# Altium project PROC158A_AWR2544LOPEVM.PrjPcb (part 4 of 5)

## Sheet PROC158A_FTDI.SchDoc
size 431 x 279 mm; Date: Not shown in title block; ApprovedBy: Not shown in title block; CheckedBy: Not shown in title block; Author: Not shown in title block; CompanyName: Not shown in title block; Engineer: Not shown in title block; Organization: Not shown in title block; Address1: Not shown in title block; Address2: Not shown in title block; Address3: Not shown in title block; Address4: Not shown in title block; DocumentNumber: 17; Revision: Use project parameter SCH_Rev; SheetNumber: 17; SheetTotal: 24; PageSetup: Record=PageOptions¦CenterHorizontal=True¦CenterVertical=True¦PrintScale=1.00¦XCorrection=1.00¦YCorrection=1.00¦PrintKind=0¦BorderSize=5000000¦LeftOffset=0¦BottomOffset=0¦Orientation=2¦PaperLength=1000¦PaperWidth=1000¦Scale=100¦PaperSource=15¦PrintQuality=600¦MediaType=1¦DitherType=10¦PaperKind=Letter¦PrintScaleMode=1
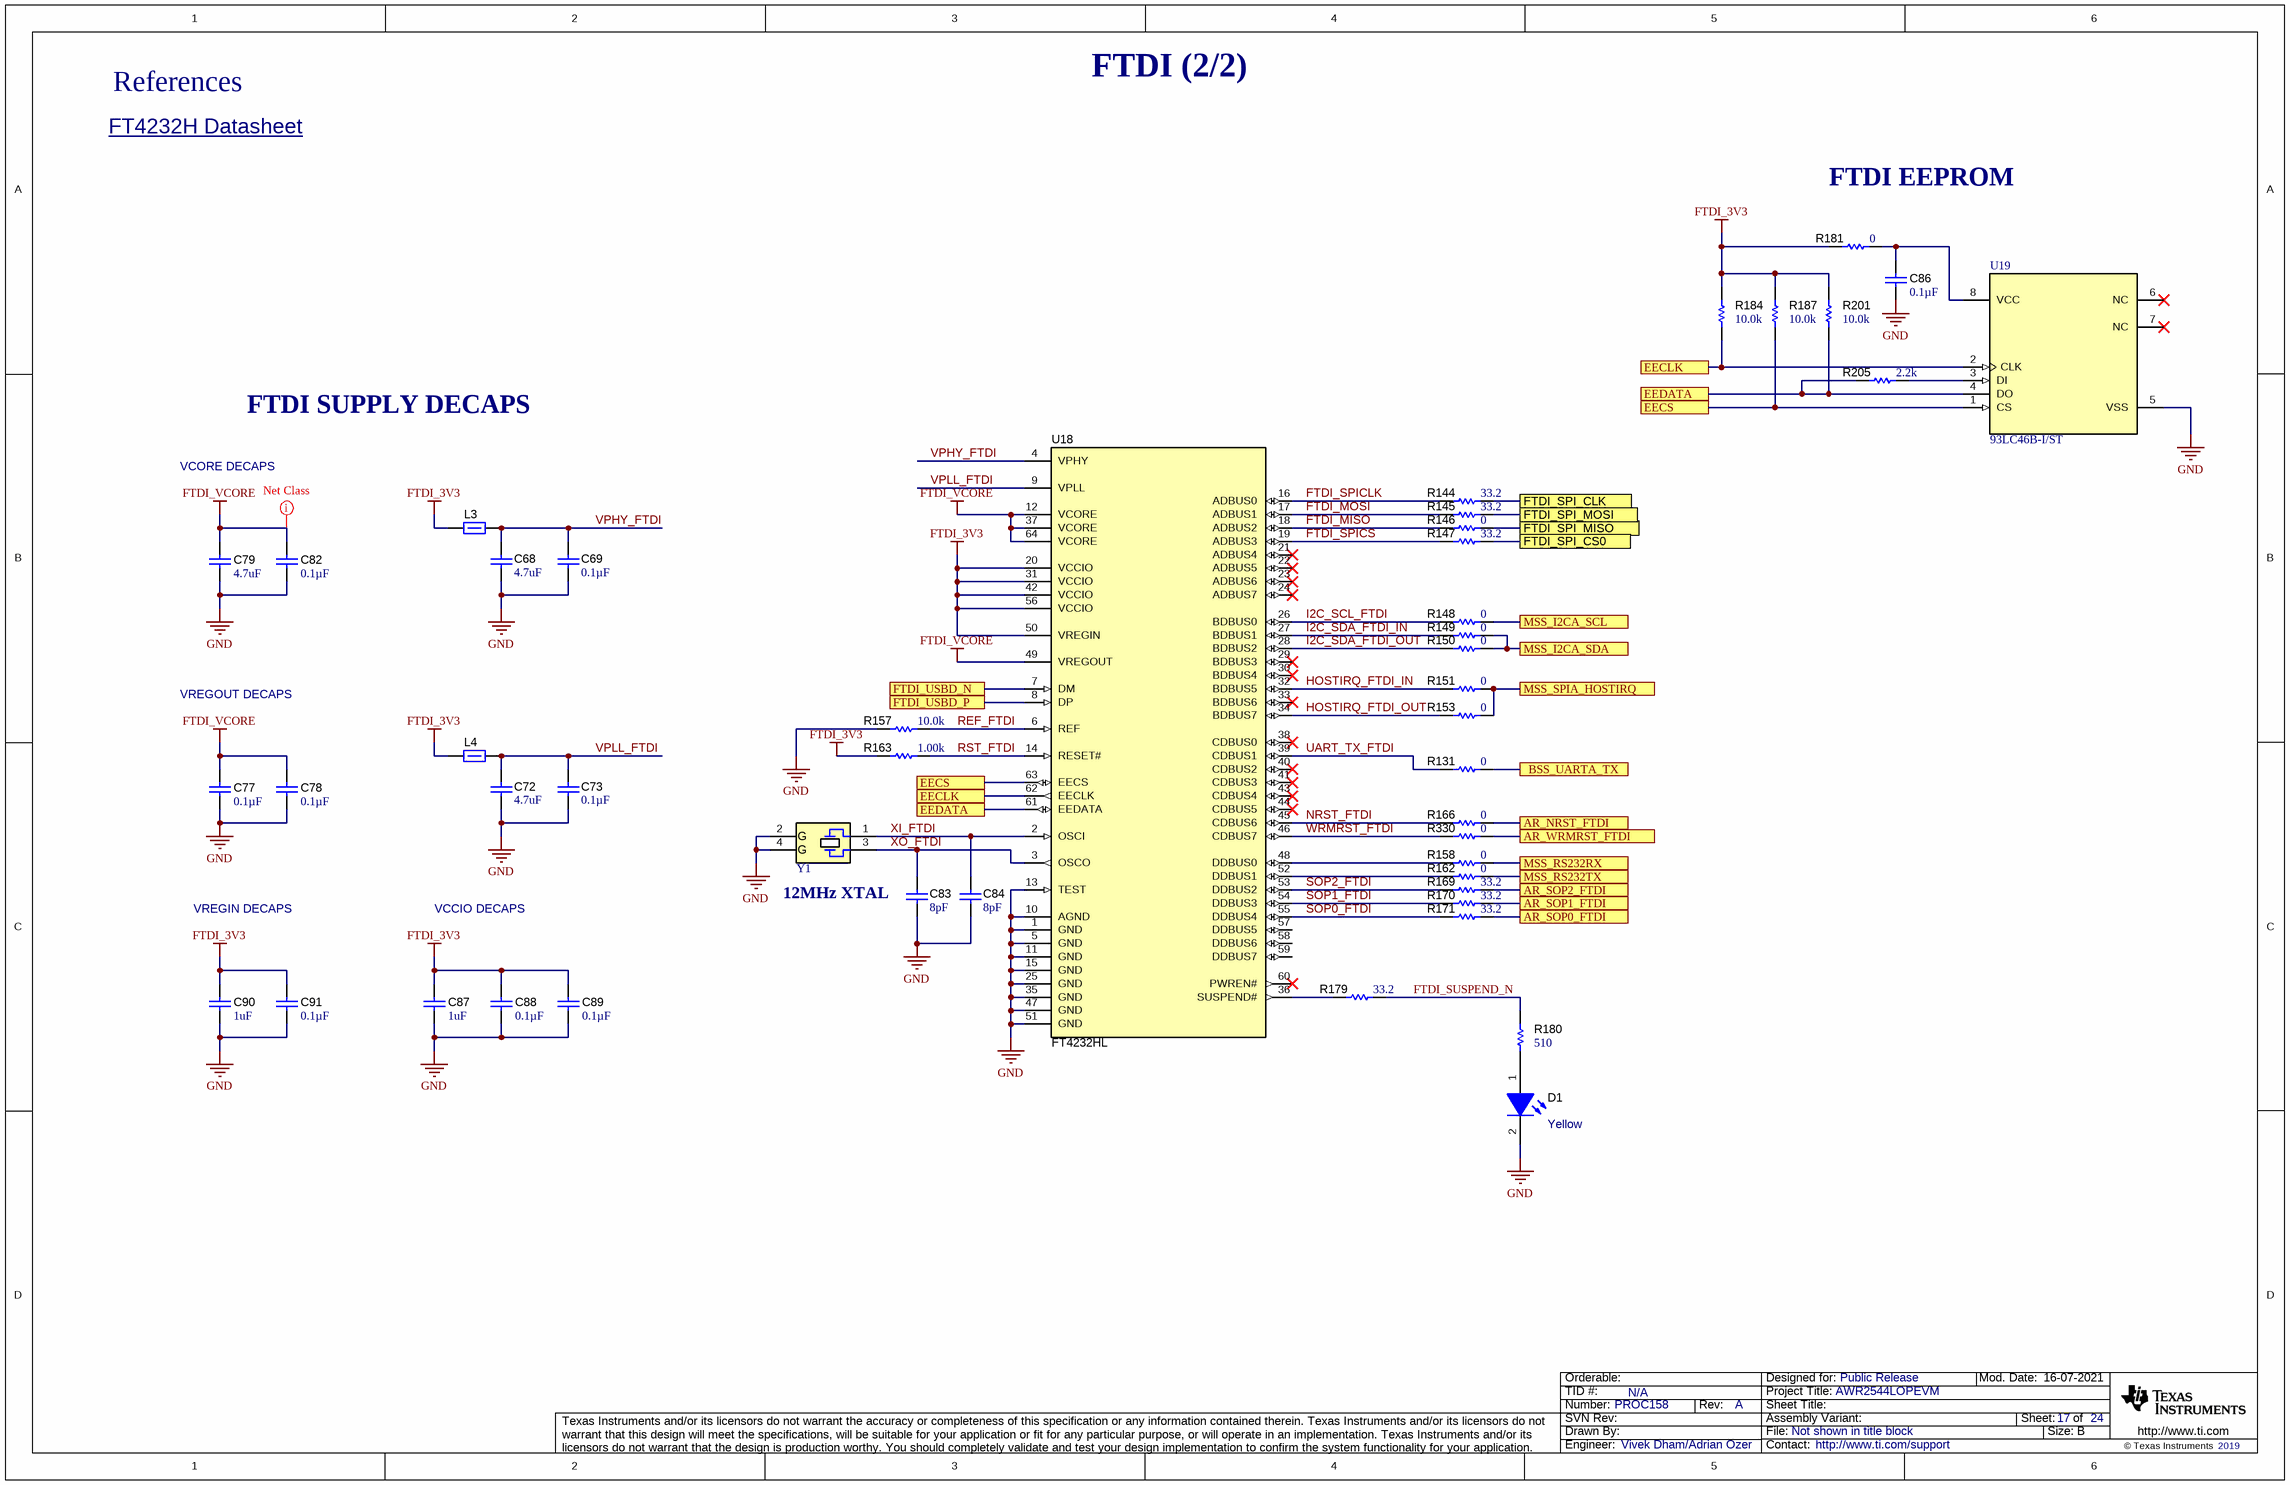
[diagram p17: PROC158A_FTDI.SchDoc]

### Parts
C68  ValueDisplayed: 4.7uF  [0603L]  (hidden comment: C1608X7S1A475K080AC)
C69  ValueDisplayed: 0.1µF  [0402L]  (hidden comment: C0402C104K8RACTU)
C72  ValueDisplayed: 4.7uF  [0603L]  (hidden comment: C1608X7S1A475K080AC)
C73  ValueDisplayed: 0.1µF  [0402L]  (hidden comment: C0402C104K8RACTU)
C77  ValueDisplayed: 0.1µF  [0402L]  (hidden comment: C0402C104K8RACTU)
C78  ValueDisplayed: 0.1µF  [0402L]  (hidden comment: C0402C104K8RACTU)
C79  ValueDisplayed: 4.7uF  [0603L]  (hidden comment: C1608X7S1A475K080AC)
C82  ValueDisplayed: 0.1µF  [0402L]  (hidden comment: C0402C104K8RACTU)
C83  Cap_F: 8pF  [0402L]  (hidden comment: GCM1555C1H8R0DA16D)
C84  Cap_F: 8pF  [0402L]  (hidden comment: GCM1555C1H8R0DA16D)
C86  ValueDisplayed: 0.1µF  [0402L]  (hidden comment: C0402C104K8RACTU)
C87  ValueDisplayed: 1uF  [0603L]  (hidden comment: GCM188R71C105KA64D)
C88  ValueDisplayed: 0.1µF  [0402L]  (hidden comment: C0402C104K8RACTU)
C89  ValueDisplayed: 0.1µF  [0402L]  (hidden comment: C0402C104K8RACTU)
C90  ValueDisplayed: 1uF  [0603L]  (hidden comment: GCM188R71C105KA64D)
C91  ValueDisplayed: 0.1µF  [0402L]  (hidden comment: C0402C104K8RACTU)
D1  value Yellow  [TLMx1000_Yellow]  (hidden comment: TLMY1000-GS08)
L3  BLM15HG601SN1D  [0402L]  (value not drawn)
L4  BLM15HG601SN1D  [0402L]  (value not drawn)
R131  ValueDisplayed: 0  [0402L]  (hidden comment: ERJ-2GE0R00X)
R144  ValueDisplayed: 33.2  [0402L]  (hidden comment: CRCW040233R2FKED)
R145  ValueDisplayed: 33.2  [0402L]  (hidden comment: CRCW040233R2FKED)
R146  ValueDisplayed: 0  [0402L]  (hidden comment: ERJ-2GE0R00X)
R147  ValueDisplayed: 33.2  [0402L]  (hidden comment: CRCW040233R2FKED)
R148  ValueDisplayed: 0  [0402L]  (hidden comment: ERJ-2GE0R00X)
R149  ValueDisplayed: 0  [0402L]  (hidden comment: ERJ-2GE0R00X)
R150  ValueDisplayed: 0  [0402L]  (hidden comment: ERJ-2GE0R00X)
R151  ValueDisplayed: 0  [0402L]  (hidden comment: ERJ-2GE0R00X)
R153  ValueDisplayed: 0  [0402L]  (hidden comment: ERJ-2GE0R00X)
R157  ValueDisplayed: 10.0k  [0402L]  (hidden comment: CRCW040210K0FKED)
R158  ValueDisplayed: 0  [0402L]  (hidden comment: ERJ-2GE0R00X)
R162  ValueDisplayed: 0  [0402L]  (hidden comment: ERJ-2GE0R00X)
R163  ValueDisplayed: 1.00k  [0402L]  (hidden comment: CRCW04021K00FKED)
R166  ValueDisplayed: 0  [0402L]  (hidden comment: ERJ-2GE0R00X)
R169  ValueDisplayed: 33.2  [0402L]  (hidden comment: CRCW040233R2FKED)
R170  ValueDisplayed: 33.2  [0402L]  (hidden comment: CRCW040233R2FKED)
R171  ValueDisplayed: 33.2  [0402L]  (hidden comment: CRCW040233R2FKED)
R179  ValueDisplayed: 33.2  [0402L]  (hidden comment: CRCW040233R2FKED)
R180  ValueDisplayed: 510  [0402L]  (hidden comment: ERJ-2GEJ511X)
R181  ValueDisplayed: 0  [0402L]  (hidden comment: ERJ-2GE0R00X)
R184  ValueDisplayed: 10.0k  [0402L]  (hidden comment: CRCW040210K0FKED)
R187  ValueDisplayed: 10.0k  [0402L]  (hidden comment: CRCW040210K0FKED)
R201  ValueDisplayed: 10.0k  [0402L]  (hidden comment: CRCW040210K0FKED)
R205  ValueDisplayed: 2.2k  [0402L]  (hidden comment: CRCW04022K20JNED)
R330  ValueDisplayed: 0  [0402L]  (hidden comment: ERJ-2GE0R00X)
U18  FT4232HL  [LQFP64_N]
U19  93LC46B-I/ST  [TSSOP-8]
Y1  NX3225SA-12.000M-STD-CRS-2  [NDK_NX3225SA]  (value not drawn)

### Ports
AR_NRST_FTDI, AR_SOP0_FTDI, AR_SOP1_FTDI, AR_SOP2_FTDI, AR_WRMRST_FTDI, BSS_UARTA_TX, EECLK, EECS, EEDATA, FTDI_SPI_CLK, FTDI_SPI_CS0, FTDI_SPI_MISO, FTDI_SPI_MOSI, FTDI_USBD_N, FTDI_USBD_P, MSS_I2CA_SCL, MSS_I2CA_SDA, MSS_RS232RX, MSS_RS232TX, MSS_SPIA_HOSTIRQ

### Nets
FTDI_3V3: C87.1 C88.1 C89.1 C90.1 C91.1 L3.1 L4.1 R163.1 R181.2 R184.2 R187.2 R201.2 U18.20(VCCIO) U18.31(VCCIO) U18.42(VCCIO) U18.50(VREGIN) U18.56(VCCIO)
FTDI_VCORE: C77.1 C78.1 C79.1 C82.1 U18.12(VCORE) U18.37(VCORE) U18.49(VREGOUT) U18.64(VCORE)
GND: C68.2 C69.1 C72.2 C73.1 C77.2 C78.2 C79.2 C82.2 C83.2 C84.2 C86.2 C87.2 C88.2 C89.2 C90.2 C91.2 D1.2(K) R157.1 U18.1(GND) U18.5(GND) U18.10(AGND) U18.11(GND) U18.13(TEST) U18.15(GND) U18.25(GND) U18.35(GND) U18.47(GND) U18.51(GND) U19.5(VSS) Y1.2(GND) Y1.4(GND)
AR_NRST_FTDI: R166.2 ; port AR_NRST_FTDI
AR_SOP0_FTDI: R171.2 ; port AR_SOP0_FTDI
AR_SOP1_FTDI: R170.2 ; port AR_SOP1_FTDI
AR_SOP2_FTDI: R169.2 ; port AR_SOP2_FTDI
AR_WRMRST_FTDI: R330.2 ; port AR_WRMRST_FTDI
BSS_UARTA_TX: R131.1 ; port BSS_UARTA_TX
EECLK: R184.1 U18.62(EECLK) U19.2(CLK) ; port EECLK
EECS: R187.1 U18.63(EECS) U19.1(CS) ; port EECS
EEDATA: R201.1 R205.1 U18.61(EEDATA) U19.4(DO) ; port EEDATA
FTDI_MISO: R146.1 U18.18(ADBUS2)
FTDI_MOSI: R145.1 U18.17(ADBUS1)
FTDI_SPI_CLK: R144.2 ; port FTDI_SPI_CLK
FTDI_SPI_CS0: R147.2 ; port FTDI_SPI_CS0
FTDI_SPI_MISO: R146.2 ; port FTDI_SPI_MISO
FTDI_SPI_MOSI: R145.2 ; port FTDI_SPI_MOSI
FTDI_SPICLK: R144.1 U18.16(ADBUS0)
FTDI_SPICS: R147.1 U18.19(ADBUS3)
FTDI_SUSPEND_N: R179.2 R180.2
FTDI_USBD_N: U18.7(DM) ; port FTDI_USBD_N
FTDI_USBD_P: U18.8(DP) ; port FTDI_USBD_P
HOSTIRQ_FTDI_IN: R151.1 U18.32(BDBUS5)
HOSTIRQ_FTDI_OUT: R153.1 U18.34(BDBUS7)
I2C_SCL_FTDI: R148.1 U18.26(BDBUS0)
I2C_SDA_FTDI_IN: R149.1 U18.27(BDBUS1)
I2C_SDA_FTDI_OUT: R150.1 U18.28(BDBUS2)
MSS_I2CA_SCL: R148.2 ; port MSS_I2CA_SCL
MSS_I2CA_SDA: R149.2 R150.2 ; port MSS_I2CA_SDA
MSS_RS232RX: R158.2 ; port MSS_RS232RX
MSS_RS232TX: R162.2 ; port MSS_RS232TX
MSS_SPIA_HOSTIRQ: R151.2 R153.2 ; port MSS_SPIA_HOSTIRQ
NRST_FTDI: R166.1 U18.45(CDBUS6)
REF_FTDI: R157.2 U18.6(REF)
RST_FTDI: R163.2 U18.14(RESET#)
SOP0_FTDI: R171.1 U18.55(DDBUS4)
SOP1_FTDI: R170.1 U18.54(DDBUS3)
SOP2_FTDI: R169.1 U18.53(DDBUS2)
UART_TX_FTDI: R131.2 U18.39(CDBUS1)
VPHY_FTDI: C68.1 C69.2 L3.2 U18.4(VPHY)
VPLL_FTDI: C72.1 C73.2 L4.2 U18.9(VPLL)
WRMRST_FTDI: R330.1 U18.46(CDBUS7)
XI_FTDI: C84.1 U18.2(OSCI) Y1.1
XO_FTDI: C83.1 U18.3(OSCO) Y1.3
NetC86_1: C86.1 R181.1 U19.8(VCC)
NetD1_1: D1.1(A) R180.1
NetR158_1: R158.1 U18.48(DDBUS0)
NetR162_1: R162.1 U18.52(DDBUS1)
NetR179_1: R179.1 U18.36(SUSPEND#)
NetR205_2: R205.2 U19.3(DI)

Not connected (* = marked no-connect by the designer): U18 21(ADBUS4)* 22(ADBUS5)* 23(ADBUS6)* 24(ADBUS7)* 29(BDBUS3)* 30(BDBUS4)* 33(BDBUS6)* 38(CDBUS0)* 40(CDBUS2)* 41(CDBUS3)* 43(CDBUS4)* 44(CDBUS5)* 57(DDBUS5) 58(DDBUS6) 59(DDBUS7) 60(PWREN#)*; U19 6(NC)* 7(NC)*

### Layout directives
net class PWR: FTDI_VCORE

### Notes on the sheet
- References
- FTDI (2/2)
- FT4232H Datasheet <https://www.ftdichip.com/Support/Documents/DataSheets/ICs/DS_FT4232H.pdf>
- FTDI EEPROM
- FTDI SUPPLY DECAPS
- VCORE DECAPS
- VREGOUT DECAPS
- 12MHz XTAL
- VREGIN DECAPS
- VCCIO DECAPS

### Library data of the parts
C68 C72 C79 = CMP-0007058-4: CAP, CERM, 4.7 uF, 10 V, +/- 10%, X7S, 0603; Manufacturer: TDK; TaMin_C: -55°C; Polarized: N; SizeAreaWB_mm2: 4.68; Value1: Unknown; U/M: EA; Value: 4.7uF; TaMax_C: 125°C; SizeZ_mm: 1; SizeX_mm: 1.6; SizeY_mm: 0.8; Cap_Case: 0603; Value2: 10V; SizeArea_mm2: 1.28; CompType: Capacitor; Cap_F: 4.7µF; AEC Category: Q200
C69 C73 C77 C78 C82 C86 C88 C89 C91 = CMP-0078241-1: CAP, CERM, 0.1 µF, 10 V,+/- 10%, X7R, 0402; Manufacturer: Kemet; TaMin_C: -55°C; Polarized: N; SizeAreaWB_mm2: 3; U/M: EA; Value: 0.1uF; TaMax_C: 125°C; SizeZ_mm: 0.6; SizeX_mm: 1; SizeY_mm: 0.5; Cap_Case: 0402; Value2: 10V; CompType: Capacitor; Cap_F: 100nF; AEC Category: Q200
C83 C84 = CMP-0087060-3: Cap Ceramic 8pF 50V C0G 0.5pF SMD 0402 125C Paper T/R; Manufacturer: Murata Electronics North America; AEC Qualified: Yes; TempCo: 30ppm/°C; AEC Grade: Grade 1; SizeZ_mm: 0.55mm
C87 C90 = CMP-0007136-5: CAP, CERM, 1 uF, 16 V, +/- 10%, X7R, AEC-Q200 Grade 1, 0603; Manufacturer: MuRata; TaMin_C: -55°C; Polarized: N; SizeAreaWB_mm2: 4.68; Value1: Unknown; U/M: EA; Value: 1uF; TaMax_C: 125°C; SizeZ_mm: 1; SizeX_mm: 1.6; SizeY_mm: 0.8; Cap_Case: 0603; Value2: 16V; SizeArea_mm2: 1.28; CompType: Capacitor; AEC Qualified: Y; Cap_F: 1µF; AEC Category: Q200
D1 = CMP-0078196-2: LED, Yellow, SMD; Manufacturer: Vishay-Semiconductor; Tjmax_C: 120°C; SizeAreaWB_mm2: 4.68; Vr_V: 6V; Power_TotalModule: 40mW; Angle: 160; SizeArea_mm2: 1.28; Ir_A: 10µA; SizeZ_mm: 0.65; Io_A: 2mA; Vf_V: 1.8V; SizeY_mm: 0.8; Value1: .04W; SizeX_mm: 1.6; Type: AlInGaP
L3 L4 = CMP-0081523-1: Ferrite Bead, 600 ohm @ 100 MHz, 0.3 A, 0402; Manufacturer: MuRata; SizeAreaWB_mm2: 3; SizeArea_mm2: 0.5; Value: 600 ohm; SizeZ_mm: 0.6; Imax_A: 3dA; ZTyp@100MHz_Ohm: 600; Value2: 0.3A; Value1: 0.7 ohm; DCR_ohm: 7d; SizeX_mm: 1; Ztyp@1GHz_Ohm: 1k
R131 R158 R162 = CMP-0026992-3: RES, 0, 5%, 0.1 W, AEC-Q200 Grade 0, 0402; Manufacturer: Panasonic; Power_W: 100mW; TempCo: 600 ppm/C; Value_Code: 0000; Value: 0; EIA_Code: E24; SizeX_mm: 1; SizeY_mm: 0.5; SizeZ_mm: 0.6; Value2: 0.1W; CompType: Resistor; AEC Qualified: Y; VDC_V: 50V; AEC Category: Q200; SizeAreaWB_mm2: 3; INSTALLATION: DNP
R144 R145 R147 R169-R171 R179 = CMP-0026299-2: RES, 33.2, 1%, 0.063 W, AEC-Q200 Grade 0, 0402; Manufacturer: Vishay-Dale; Power_W: 63mW; TempCo: 100 ppm/C; Value_Code: 33R2; Value: 33.2; EIA_Code: E96; SizeX_mm: 1; SizeY_mm: 0.5; SizeZ_mm: 0.6; Value2: 0.063W; AEC Qualified: Y; VDC_V: 50V; AEC Category: Q200; AEC Grade: 0
R146 R148-R151 R153 R166 R181 R330 = CMP-0026992-3: RES, 0, 5%, 0.1 W, AEC-Q200 Grade 0, 0402; Manufacturer: Panasonic; Power_W: 100mW; TempCo: 600 ppm/C; Value_Code: 0000; Value: 0; EIA_Code: E24; SizeX_mm: 1; SizeY_mm: 0.5; SizeZ_mm: 0.6; Value2: 0.1W; AEC Qualified: Y; VDC_V: 50V; AEC Category: Q200; SizeAreaWB_mm2: 3
R157 R184 R187 R201 = CMP-0025958-3: RES, 10.0 k, 1%, 0.063 W, AEC-Q200 Grade 0, 0402; Manufacturer: Vishay-Dale; Power_W: 63mW; TempCo: 100 ppm/C; Value_Code: 10k0; Value: 10.0k; EIA_Code: E96; Res_ohm: 10k; SizeX_mm: 1; SizeY_mm: 0.5; SizeZ_mm: 0.6; Value2: 0.063W; AEC Qualified: Y; VDC_V: 50V; AEC Category: Q200; AEC Grade: 0
R163 = CMP-0026071-3: RES, 1.00 k, 1%, 0.063 W, AEC-Q200 Grade 0, 0402; Manufacturer: Vishay-Dale; Power_W: 63mW; TempCo: 100 ppm/C; Value_Code: 1k00; Value: 1.00k; EIA_Code: E96; Res_ohm: 1k; SizeX_mm: 1; SizeY_mm: 0.5; SizeZ_mm: 0.6; Value2: 0.063W; AEC Qualified: Y; VDC_V: 50V; AEC Category: Q200; AEC Grade: 0
R180 = CMP-0078212-1: RES, 510, 5%, 0.1 W, AEC-Q200 Grade 0, 0402; Manufacturer: Panasonic; Value_Code: 510R; SizeArea_mm2: 0.5; AEC Qualified: Y; AEC Category: Q200; Value: 510; SizeZ_mm: 0.6; EIA_Code: E24; TempCo: 200 ppm/C; AEC Grade: 0; Power_W: 100mW; VDC_V: 50V; Value2: 0.1W; U/M: EA; SizeX_mm: 1
R205 = CMP-0026890-5: RES, 2.2 k, 5%, 0.063 W, AEC-Q200 Grade 0, 0402; Manufacturer: Vishay-Dale; Power_W: 63mW; TempCo: 200 ppm/C; Value_Code: 2k20; Value: 2.2k; EIA_Code: E24; SizeX_mm: 1; SizeY_mm: 0.5; SizeZ_mm: 0.6; Value2: 0.063W; AEC Qualified: Y; VDC_V: 50V; AEC Category: Q200; AEC Grade: 0
U18 = CMP-0004747-1: Quad High Speed USB to Multipurpose UART/MPSSE IC; Manufacturer: FTDI
U19 = CMP-0081524-1: 1K Microwire Compatible Serial EEPROM, TSSOP-8; Manufacturer: Microchip; SizeArea_mm2: 19.2; SizeAreaWB_mm2: 42; SizeY_mm: 3; SizeZ_mm: 1.2; SizeX_mm: 6.4
Y1 = CMP-0081529-1: Crystal, 12 MHz, 15 ppm, 8 pF, AEC-Q200 Grade 1, SMD; Manufacturer: NDK; TaMin_C: -40°C; Frequency Tolerance: 15 ppm; Frequency Stability: 50 ppm; Load Capacitance: 8 pF; Frequency_Fixed: 12MHz; TaMax_C: 125°C; AEC Qualified: Y; AEC Grade: 1; AEC Category: Q200

## Sheet PROC158A_XDS110 Interface_1A.SchDoc
size 431 x 279 mm; Date: Not shown in title block; ApprovedBy: Not shown in title block; CheckedBy: Not shown in title block; Author: Not shown in title block; CompanyName: Not shown in title block; Engineer: Not shown in title block; Organization: Not shown in title block; Address1: Not shown in title block; Address2: Not shown in title block; Address3: Not shown in title block; Address4: Not shown in title block; DocumentNumber: 18; Revision: Use project parameter SCH_Rev; SheetNumber: 18; SheetTotal: 24; PageSetup: Record=PageOptions¦CenterHorizontal=True¦CenterVertical=True¦PrintScale=1.00¦XCorrection=1.00¦YCorrection=1.00¦PrintKind=0¦BorderSize=5000000¦LeftOffset=0¦BottomOffset=0¦Orientation=2¦PaperLength=1000¦PaperWidth=1000¦Scale=100¦PaperSource=15¦PrintQuality=600¦MediaType=1¦DitherType=10¦PaperKind=Letter¦PrintScaleMode=1
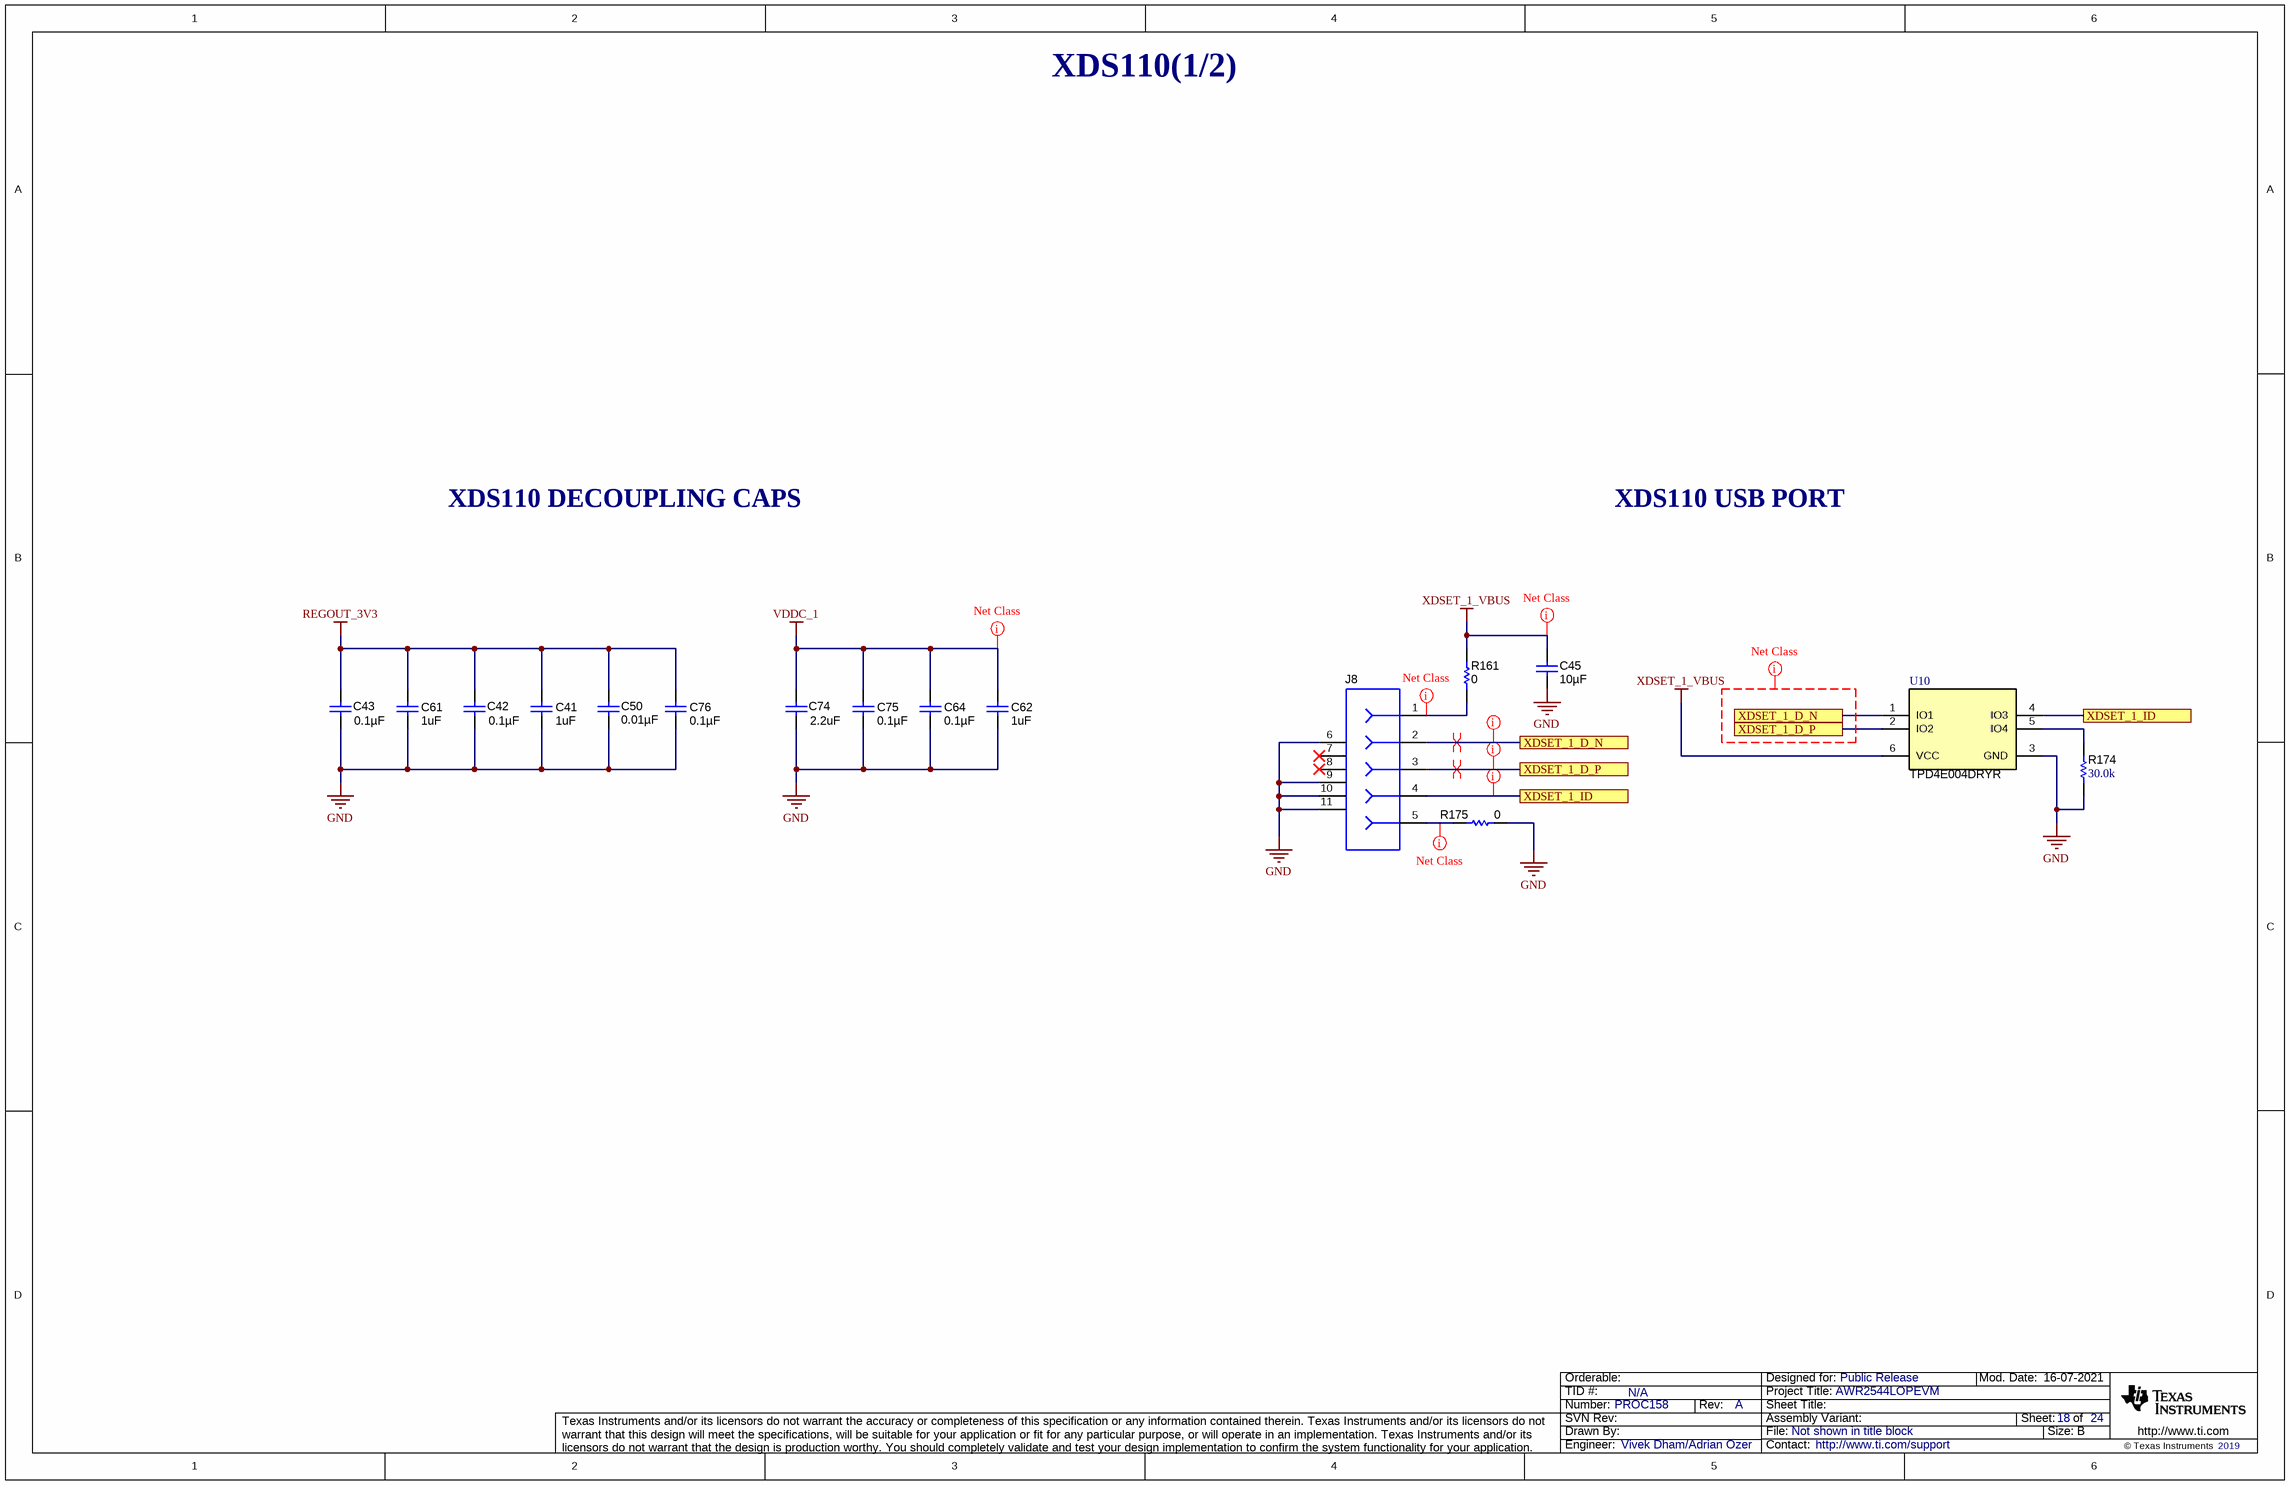
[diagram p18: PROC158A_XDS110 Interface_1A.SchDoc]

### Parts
C41  ValueDisplayed: 1uF  [0402_070]  (hidden comment: GCM155C71A105KE38D)
C42  ValueDisplayed: 0.1µF  [0402L]  (hidden comment: C0402C104K8RACTU)
C43  ValueDisplayed: 0.1µF  [0402L]  (hidden comment: C0402C104K8RACTU)
C45  Cap_F: 10µF  [0805L]  (hidden comment: CL21B106KOQNNNE)
C50  ValueDisplayed: 0.01µF  [0402L]  (hidden comment: C0402C103K4RACTU)
C61  ValueDisplayed: 1uF  [0402_070]  (hidden comment: GCM155C71A105KE38D)
C62  ValueDisplayed: 1uF  [0402_070]  (hidden comment: GCM155C71A105KE38D)
C64  ValueDisplayed: 0.1µF  [0402L]  (hidden comment: C0402C104K8RACTU)
C74  ValueDisplayed: 2.2uF  [0402_065L]  (hidden comment: C1005X7S1A225K050BC)
C75  ValueDisplayed: 0.1µF  [0402L]  (hidden comment: C0402C104K8RACTU)
C76  ValueDisplayed: 0.1µF  [0402L]  (hidden comment: C0402C104K8RACTU)
J8  105017-0001  [CONN_105017-0001]  (value not drawn)
R161  ValueDisplayed: 0  [0603L]  (hidden comment: MCT06030Z0000ZP500)
R174  ValueDisplayed: 30.0k  [0402L]  (hidden comment: CRCW040230K0FKED)
R175  ValueDisplayed: 0  [0603L]  (hidden comment: MCT06030Z0000ZP500)
U10  TPD4E004DRYR  [DRY0006A]

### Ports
XDSET_1_D_N, XDSET_1_D_P, XDSET_1_ID

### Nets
GND: C41.2 C42.1 C43.1 C45.2 C50.2 C61.2 C62.2 C64.1 C74.1 C75.1 C76.1 J8.6 J8.9 J8.10 J8.11 R174.1 R175.1 U10.3(GND)
REGOUT_3V3: C41.1 C42.2 C43.2 C50.1 C61.1 C76.2
VDDC_1: C62.1 C64.2 C74.2 C75.2
XDSET_1_VBUS: C45.1 R161.2 U10.6(VCC)
XDSET_1_D_N: J8.2 U10.1(IO1) ; port XDSET_1_D_N
XDSET_1_D_P: J8.3 U10.2(IO2) ; port XDSET_1_D_P
XDSET_1_ID: J8.4 U10.4(IO3) ; port XDSET_1_ID
NetJ8_1: J8.1 R161.1
NetJ8_5: J8.5 R175.2
NetR174_2: R174.2 U10.5(IO4)

Not connected (* = marked no-connect by the designer): J8 7* 8*

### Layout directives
differential pair: XDSET_1_D_N, XDSET_1_D_P
net class XDS_USB: XDSET_1_D_N, XDSET_1_D_P, XDSET_1_ID
net class PWR: NetJ8_1, NetJ8_5, VDDC_1, XDSET_1_VBUS
net class USB_DIFF: (no net found under the mark)

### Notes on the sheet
- XDS110(1/2)
- XDS110 DECOUPLING CAPS
- XDS110 USB PORT

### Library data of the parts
C41 C61 C62 = CMP-0006349-2: CAP, CERM, 1 uF, 10 V, +/- 10%, X7S, AEC-Q200 Grade 1, 0402; Manufacturer: MuRata; TaMin_C: -55°C; Polarized: N; SizeAreaWB_mm2: 3; Value1: Unknown; U/M: EA; Value: 1uF; TaMax_C: 125°C; SizeZ_mm: 0.7; SizeX_mm: 1; SizeY_mm: 0.5; Cap_Case: 0402; Value2: 10V; AEC Qualified: Y; Cap_F: 1µF; AEC Category: Q200
C42 C43 C64 C75 C76 = CMP-0078241-1: CAP, CERM, 0.1 µF, 10 V,+/- 10%, X7R, 0402; Manufacturer: Kemet; TaMin_C: -55°C; Polarized: N; SizeAreaWB_mm2: 3; U/M: EA; Value: 0.1uF; TaMax_C: 125°C; SizeZ_mm: 0.6; SizeX_mm: 1; SizeY_mm: 0.5; Cap_Case: 0402; Value2: 10V; Cap_F: 100nF; AEC Category: Q200
C45 = CMP-0007995-2: CAP, CERM, 10 uF, 16 V, +/- 10%, X7R, 0805; Manufacturer: Samsung Electro-Mechanics; TaMin_C: -55°C; Polarized: N; SizeAreaWB_mm2: 6.75; Value1: Unknown; U/M: EA; Value: 10uF; TaMax_C: 125°C; SizeZ_mm: 1.45; SizeX_mm: 2; SizeY_mm: 1.25; Cap_Case: 0805; Value2: 16V; SizeArea_mm2: 2.5; AEC Category: Q200
C50 = CMP-0078218-1: CAP, CERM, 0.01 µF, 16 V,+/- 10%, X7R, 0402; Manufacturer: Kemet; TaMin_C: -55°C; Polarized: N; Green_Lifecycle: Active; SizeAreaWB_mm2: 3; Green_REACh: Passed; U/M: EA; Value: 0.01uF; TaMax_C: 125°C; SizeZ_mm: 0.6; SizeX_mm: 1; SizeY_mm: 0.5; Cap_Case: 0402; Value2: 16V; Cap_F: 10nF; AEC Category: Q200
C74 = CMP-0006302-2: CAP, CERM, 2.2 uF, 10 V, +/- 10%, X7S, 0402; Manufacturer: TDK; TaMin_C: -55°C; ESR_ohm: 5.925m; Polarized: N; SizeAreaWB_mm2: 3; Value1: 0.005925 ohm; U/M: EA; Value: 2.2uF; TaMax_C: 125°C; SizeZ_mm: 0.65; SizeX_mm: 1; SizeY_mm: 0.5; Cap_Case: 0402_065; Value2: 10V; CompType: Capacitor; Cap_F: 2.2µF; IRMS_A: 2.05591A; AEC Category: Q200
J8 = CMP-0055293-1: Connector, Receptacle, Micro-USB Type B, R/A, Bottom Mount SMT; Manufacturer: Molex; CNHeader: FALSE; Green_Lifecycle: Active; Gender: Female; Green_REACh: Passed; CompType: USB; CT: TRUE
R161 R175 = CMP-0025884-3: RES, 0, 5%, 0.125 W, 0603; Manufacturer: Vishay/Beyschlag; Power_W: 125mW; TempCo: ppm/C; Value_Code: 0000; U/M: EA; Value: 0; EIA_Code: E24; SizeX_mm: 1.6; SizeY_mm: 0.8; SizeZ_mm: 1; Value2: 0.125W; SizeArea_mm2: 1.28; AEC Qualified: N; AEC Category: Q200
R174 = CMP-0078244-2: RES, 30.0 k, 1%, 0.063 W, AEC-Q200 Grade 0, 0402; Manufacturer: Vishay-Dale; Power_W: 63mW; Green_Lifecycle: Active; TempCo: 100 ppm/C; Value_Code: 30k0; Green_REACh: Passed; Value: 30.0k; Res_ohm: 30k; SizeX_mm: 1; SizeY_mm: 0.5; SizeZ_mm: 0.6; Value2: 0.063W; AEC Qualified: Y; VDC_V: 50V; AEC Grade: 0; AEC Category: Q200
U10 = CMP-0043115-3: 4-Channel ESD Protection Array for High-Speed Data Interfaces, DRY0006A (USON-6); Manufacturer: Texas Instruments; IO Leakage Current(nA): 1; USB High Speed: TRUE; IO Capacitance(Typ)(pF): 1.6; Eco-Plan: Green (RoHS & no Sb/Br); IEC 61000-4-2 Contact(+/- kV): 8; Breakdown Voltage(Min)(V): 6; IEC 61000-4-2 Air-Gap(+/- kV): 12; AEC Category: Q200; AEC Qualified: N; CompType: IC; SizeArea_mm2: 1.45; SizeAreaWB_mm2: 4.9; SizeX_mm: 1.0; SizeZ_mm: 0.6; Rating: Catalog

## Sheet PROC158A_XDS110 Interface_1B.SchDoc
size 431 x 279 mm; Date: Not shown in title block; ApprovedBy: Not shown in title block; CheckedBy: Not shown in title block; Author: Not shown in title block; CompanyName: Not shown in title block; Engineer: Not shown in title block; Organization: Not shown in title block; Address1: Not shown in title block; Address2: Not shown in title block; Address3: Not shown in title block; Address4: Not shown in title block; DocumentNumber: 19; Revision: Use project parameter SCH_Rev; SheetNumber: 19; SheetTotal: 24; PageSetup: Record=PageOptions¦CenterHorizontal=True¦CenterVertical=True¦PrintScale=1.00¦XCorrection=1.00¦YCorrection=1.00¦PrintKind=0¦BorderSize=5000000¦LeftOffset=0¦BottomOffset=0¦Orientation=2¦PaperLength=1000¦PaperWidth=1000¦Scale=100¦PaperSource=15¦PrintQuality=600¦MediaType=1¦DitherType=10¦PaperKind=Letter¦PrintScaleMode=1
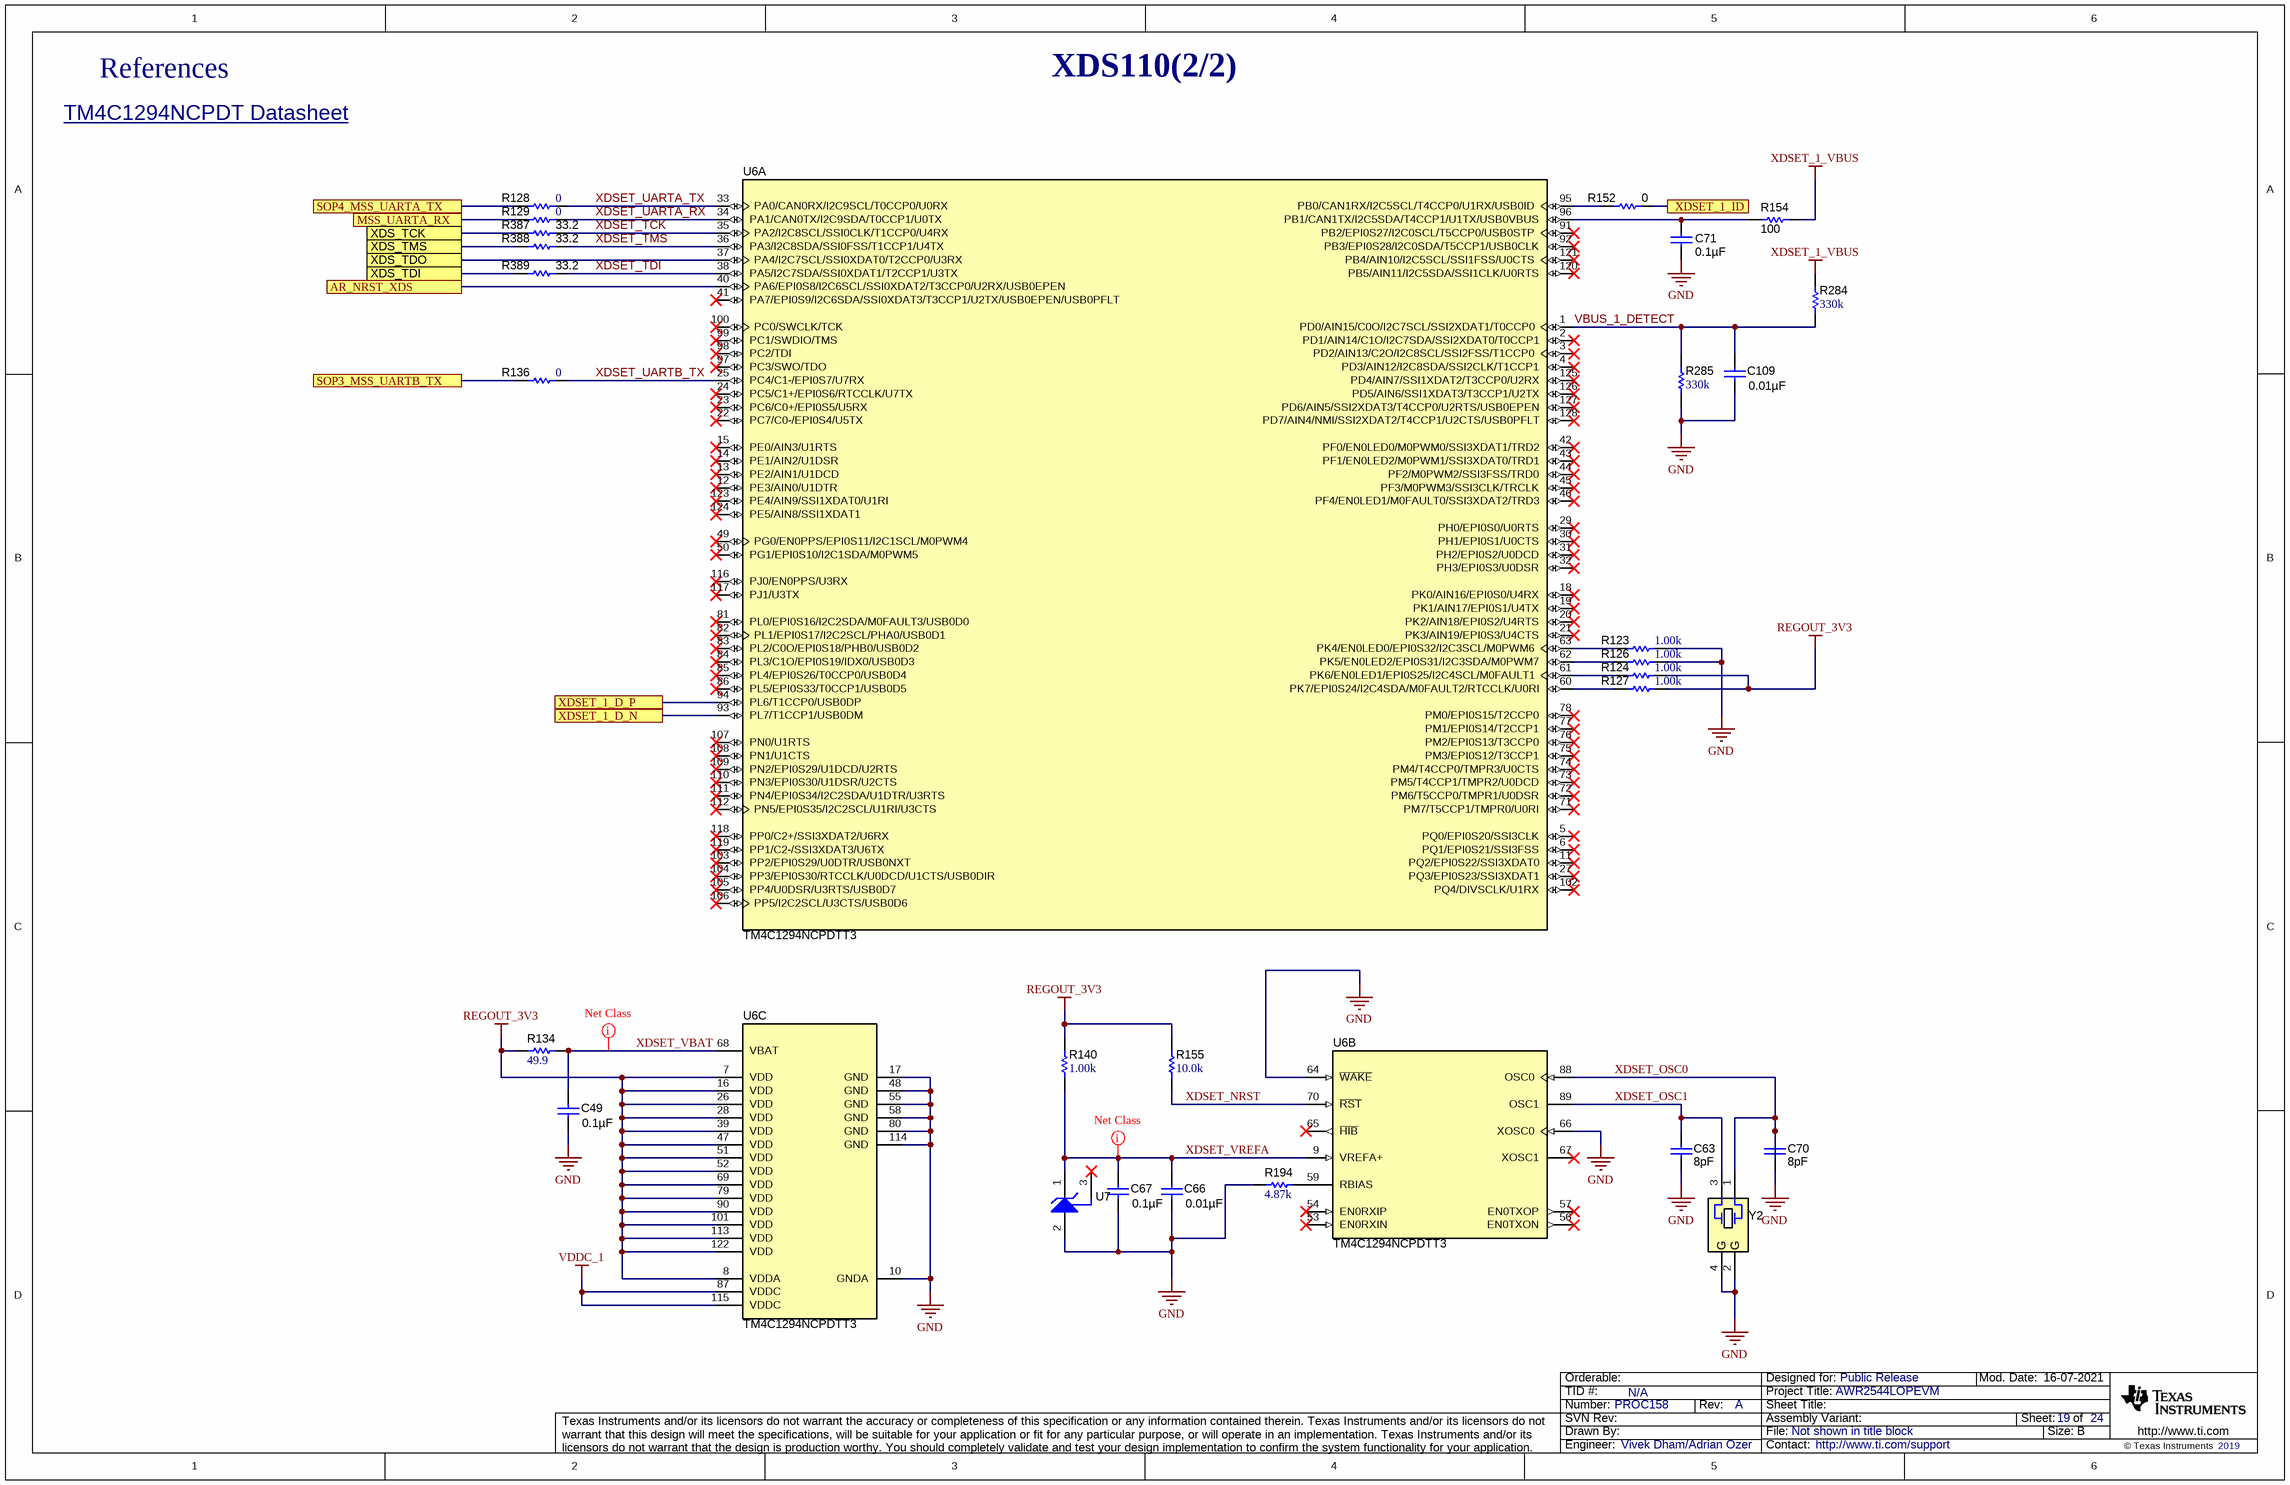
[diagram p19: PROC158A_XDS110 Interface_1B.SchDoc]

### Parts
C49  ValueDisplayed: 0.1µF  [0402L]  (hidden comment: C0402C104K8RACTU)
C63  Cap_F: 8pF  [0402L]  (hidden comment: GCM1555C1H8R0DA16D)
C66  ValueDisplayed: 0.01µF  [0402L]  (hidden comment: C0402C103K4RACTU)
C67  ValueDisplayed: 0.1µF  [0402L]  (hidden comment: C0402C104K8RACTU)
C70  Cap_F: 8pF  [0402L]  (hidden comment: GCM1555C1H8R0DA16D)
C71  ValueDisplayed: 0.1µF  [0402L]  (hidden comment: C0402C104K8RACTU)
C109  ValueDisplayed: 0.01µF  [0402L]  (hidden comment: C0402C103K4RACTU)
R123  ValueDisplayed: 1.00k  [0402L]  (hidden comment: CRCW04021K00FKED)
R124  ValueDisplayed: 1.00k  [0402L]  (hidden comment: CRCW04021K00FKED)
R126  ValueDisplayed: 1.00k  [0402L]  (hidden comment: CRCW04021K00FKED)
R127  ValueDisplayed: 1.00k  [0402L]  (hidden comment: CRCW04021K00FKED)
R128  ValueDisplayed: 0  [0402L]  (hidden comment: ERJ-2GE0R00X)
R129  ValueDisplayed: 0  [0402L]  (hidden comment: ERJ-2GE0R00X)
R134  ValueDisplayed: 49.9  [0402L]  (hidden comment: CRCW040249R9FKED)
R136  ValueDisplayed: 0  [0402L]  (hidden comment: ERJ-2GE0R00X)
R140  ValueDisplayed: 1.00k  [0402L]  (hidden comment: CRCW04021K00FKED)
R152  ValueDisplayed: 0  [0402L]  (hidden comment: ERJ-2GE0R00X)
R154  ValueDisplayed: 100  [0402L]  (hidden comment: ERJ-2GEJ101X)
R155  ValueDisplayed: 10.0k  [0402L]  (hidden comment: CRCW040210K0FKED)
R194  ValueDisplayed: 4.87k  [0402L]  (hidden comment: CRCW04024K87FKED)
R284  ValueDisplayed: 330k  [0402L]  (hidden comment: CRCW0402330KFKED)
R285  ValueDisplayed: 330k  [0402L]  (hidden comment: CRCW0402330KFKED)
R387  ValueDisplayed: 33.2  [0402L]  (hidden comment: CRCW040233R2FKED)
R388  ValueDisplayed: 33.2  [0402L]  (hidden comment: CRCW040233R2FKED)
R389  ValueDisplayed: 33.2  [0402L]  (hidden comment: CRCW040233R2FKED)
U6  TM4C1294NCPDTT3  [PDT0128A]  (parts A,B,C of 3)
U7  LM4040C25QDBZR  [DBZ0003A_N]  (value not drawn)
Y2  NX3225SA-16.000M-STD-CRS-2  [NDK_NX3225SA]  (value not drawn)

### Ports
AR_NRST_XDS, MSS_UARTA_RX, SOP3_MSS_UARTB_TX, SOP4_MSS_UARTA_TX, XDS_TCK, XDS_TDI, XDS_TDO, XDS_TMS, XDSET_1_D_N, XDSET_1_D_P, XDSET_1_ID

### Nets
GND: C49.2 C63.1 C66.1 C67.1 C70.2 C71.1 C109.1 R123.2 R126.2 R194.1 R285.1 U6.10(GNDA) U6.17(GND) U6.48(GND) U6.55(GND) U6.58(GND) U6.64(~{WAKE}) U6.66(XOSC0) U6.80(GND) U6.114(GND) U7.2(ANODE) Y2.2(GND) Y2.4(GND)
REGOUT_3V3: R124.2 R127.2 R134.2 R140.2 R155.2 U6.7(VDD) U6.8(VDDA) U6.16(VDD) U6.26(VDD) U6.28(VDD) U6.39(VDD) U6.47(VDD) U6.51(VDD) U6.52(VDD) U6.69(VDD) U6.79(VDD) U6.90(VDD) U6.101(VDD) U6.113(VDD) U6.122(VDD)
VDDC_1: U6.87(VDDC) U6.115(VDDC)
XDSET_1_VBUS: R154.2 R284.2
AR_NRST_XDS: U6.40(PA6/EPI0S8/I2C6SCL/SSI0XDAT2/T3CCP0/U2RX/USB0EPEN) ; port AR_NRST_XDS
MSS_UARTA_RX: R129.1 ; port MSS_UARTA_RX
SOP3_MSS_UARTB_TX: R136.1 ; port SOP3_MSS_UARTB_TX
SOP4_MSS_UARTA_TX: R128.1 ; port SOP4_MSS_UARTA_TX
VBUS_1_DETECT: C109.2 R284.1 R285.2 U6.1(PD0/AIN15/C0O/I2C7SCL/SSI2XDAT1/T0CCP0)
XDS_TCK: R387.1 ; port XDS_TCK
XDS_TDI: R389.1 ; port XDS_TDI
XDS_TDO: U6.37(PA4/I2C7SCL/SSI0XDAT0/T2CCP0/U3RX) ; port XDS_TDO
XDS_TMS: R388.1 ; port XDS_TMS
XDSET_1_D_N: U6.93(PL7/T1CCP1/USB0DM) ; port XDSET_1_D_N
XDSET_1_D_P: U6.94(PL6/T1CCP0/USB0DP) ; port XDSET_1_D_P
XDSET_1_ID: R152.1 ; port XDSET_1_ID
XDSET_NRST: R155.1 U6.70(~{RST})
XDSET_OSC0: C70.1 U6.88(OSC0) Y2.1
XDSET_OSC1: C63.2 U6.89(OSC1) Y2.3
XDSET_TCK: R387.2 U6.35(PA2/I2C8SCL/SSI0CLK/T1CCP0/U4RX)
XDSET_TDI: R389.2 U6.38(PA5/I2C7SDA/SSI0XDAT1/T2CCP1/U3TX)
XDSET_TMS: R388.2 U6.36(PA3/I2C8SDA/SSI0FSS/T1CCP1/U4TX)
XDSET_UARTA_RX: R129.2 U6.34(PA1/CAN0TX/I2C9SDA/T0CCP1/U0TX)
XDSET_UARTA_TX: R128.2 U6.33(PA0/CAN0RX/I2C9SCL/T0CCP0/U0RX)
XDSET_UARTB_TX: R136.2 U6.25(PC4/C1-/EPI0S7/U7RX)
XDSET_VBAT: C49.1 R134.1 U6.68(VBAT)
XDSET_VREFA: C66.2 C67.2 R140.1 U6.9(VREFA+) U7.1(CATHODE)
NetC71_2: C71.2 R154.1 U6.96(PB1/CAN1TX/I2C5SDA/T4CCP1/U1TX/USB0VBUS)
NetR123_1: R123.1 U6.63(PK4/EN0LED0/EPI0S32/I2C3SCL/M0PWM6)
NetR124_1: R124.1 U6.61(PK6/EN0LED1/EPI0S25/I2C4SCL/M0FAULT1)
NetR126_1: R126.1 U6.62(PK5/EN0LED2/EPI0S31/I2C3SDA/M0PWM7)
NetR127_1: R127.1 U6.60(PK7/EPI0S24/I2C4SDA/M0FAULT2/RTCCLK/U0RI)
NetR152_2: R152.2 U6.95(PB0/CAN1RX/I2C5SCL/T4CCP0/U1RX/USB0ID)
NetR194_2: R194.2 U6.59(RBIAS)

Not connected (* = marked no-connect by the designer): U6 2(PD1/AIN14/C1O/I2C7SDA/SSI2XDAT0/T0CCP1)* 3(PD2/AIN13/C2O/I2C8SCL/SSI2FSS/T1CCP0)* 4(PD3/AIN12/I2C8SDA/SSI2CLK/T1CCP1)* 5(PQ0/EPI0S20/SSI3CLK)* 6(PQ1/EPI0S21/SSI3FSS)* 11(PQ2/EPI0S22/SSI3XDAT0)* 12(PE3/AIN0/U1DTR)* 13(PE2/AIN1/U1DCD)* 14(PE1/AIN2/U1DSR)* 15(PE0/AIN3/U1RTS)* 18(PK0/AIN16/EPI0S0/U4RX)* 19(PK1/AIN17/EPI0S1/U4TX)* 20(PK2/AIN18/EPI0S2/U4RTS)* 21(PK3/AIN19/EPI0S3/U4CTS)* 22(PC7/C0-/EPI0S4/U5TX)* 23(PC6/C0+/EPI0S5/U5RX)* 24(PC5/C1+/EPI0S6/RTCCLK/U7TX)* 27(PQ3/EPI0S23/SSI3XDAT1)* 29(PH0/EPI0S0/U0RTS)* 30(PH1/EPI0S1/U0CTS)* 31(PH2/EPI0S2/U0DCD)* 32(PH3/EPI0S3/U0DSR)* 41(PA7/EPI0S9/I2C6SDA/SSI0XDAT3/T3CCP1/U2TX/USB0EPEN/USB0PFLT)* 42(PF0/EN0LED0/M0PWM0/SSI3XDAT1/TRD2)* 43(PF1/EN0LED2/M0PWM1/SSI3XDAT0/TRD1)* 44(PF2/M0PWM2/SSI3FSS/TRD0)* 45(PF3/M0PWM3/SSI3CLK/TRCLK)* 46(PF4/EN0LED1/M0FAULT0/SSI3XDAT2/TRD3)* 49(PG0/EN0PPS/EPI0S11/I2C1SCL/M0PWM4)* 50(PG1/EPI0S10/I2C1SDA/M0PWM5)* 53(EN0RXIN)* 54(EN0RXIP)* 56(EN0TXON)* 57(EN0TXOP)* 65(~{HIB})* 67(XOSC1)* 71(PM7/T5CCP1/TMPR0/U0RI)* 72(PM6/T5CCP0/TMPR1/U0DSR)* 73(PM5/T4CCP1/TMPR2/U0DCD)* 74(PM4/T4CCP0/TMPR3/U0CTS)* 75(PM3/EPI0S12/T3CCP1)* 76(PM2/EPI0S13/T3CCP0)* 77(PM1/EPI0S14/T2CCP1)* 78(PM0/EPI0S15/T2CCP0)* 81(PL0/EPI0S16/I2C2SDA/M0FAULT3/USB0D0)* 82(PL1/EPI0S17/I2C2SCL/PHA0/USB0D1)* 83(PL2/C0O/EPI0S18/PHB0/USB0D2)* 84(PL3/C1O/EPI0S19/IDX0/USB0D3)* 85(PL4/EPI0S26/T0CCP0/USB0D4)* 86(PL5/EPI0S33/T0CCP1/USB0D5)* 91(PB2/EPI0S27/I2C0SCL/T5CCP0/USB0STP)* 92(PB3/EPI0S28/I2C0SDA/T5CCP1/USB0CLK)* 97(PC3/SWO/TDO)* 98(PC2/TDI)* 99(PC1/SWDIO/TMS)* 100(PC0/SWCLK/TCK)* 102(PQ4/DIVSCLK/U1RX)* 103(PP2/EPI0S29/U0DTR/USB0NXT)* 104(PP3/EPI0S30/RTCCLK/U0DCD/U1CTS/USB0DIR)* 105(PP4/U0DSR/U3RTS/USB0D7)* 106(PP5/I2C2SCL/U3CTS/USB0D6)* 107(PN0/U1RTS)* 108(PN1/U1CTS)* 109(PN2/EPI0S29/U1DCD/U2RTS)* 110(PN3/EPI0S30/U1DSR/U2CTS)* 111(PN4/EPI0S34/I2C2SDA/U1DTR/U3RTS)* 112(PN5/EPI0S35/I2C2SCL/U1RI/U3CTS)* 116(PJ0/EN0PPS/U3RX)* 117(PJ1/U3TX)* 118(PP0/C2+/SSI3XDAT2/U6RX)* 119(PP1/C2-/SSI3XDAT3/U6TX)* 120(PB5/AIN11/I2C5SDA/SSI1CLK/U0RTS)* 121(PB4/AIN10/I2C5SCL/SSI1FSS/U0CTS)* 123(PE4/AIN9/SSI1XDAT0/U1RI)* 124(PE5/AIN8/SSI1XDAT1)* 125(PD4/AIN7/SSI1XDAT2/T3CCP0/U2RX)* 126(PD5/AIN6/SSI1XDAT3/T3CCP1/U2TX)* 127(PD6/AIN5/SSI2XDAT3/T4CCP0/U2RTS/USB0EPEN)* 128(PD7/AIN4/NMI/SSI2XDAT2/T4CCP1/U2CTS/USB0PFLT)*; U7 3(NC)*

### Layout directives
net class PWR: XDSET_VBAT, XDSET_VREFA

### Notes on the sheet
- References
- XDS110(2/2)
- TM4C1294NCPDT Datasheet <http://www.ti.com/lit/ds/symlink/tm4c1294ncpdt.pdf>

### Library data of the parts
C49 = CMP-0078241-1: as C69 on sheet PROC158A_FTDI
C63 C70 = CMP-0087060-3: Cap Ceramic 8pF 50V C0G 0.5pF SMD 0402 125C Paper T/R; Manufacturer: Murata Electronics North America; TempCo: 30ppm/°C; AEC Qualified: Yes; AEC Grade: Grade 1; SizeZ_mm: 0.55mm
C66 C109 = CMP-0078218-1: as C50 on sheet PROC158A_XDS110 Interface_1A
C67 C71 = CMP-0078241-1: as C42 on sheet PROC158A_XDS110 Interface_1A
R123 R124 R126 R127 R140 = CMP-0026071-3: as R163 on sheet PROC158A_FTDI
R128 R129 R136 = CMP-0026992-3: as R131 on sheet PROC158A_FTDI
R134 = CMP-0026404-2: RES, 49.9, 1%, 0.063 W, AEC-Q200 Grade 0, 0402; Manufacturer: Vishay-Dale; Power_W: 63mW; TempCo: 100 ppm/C; Value_Code: 49R9; Value: 49.9; EIA_Code: E96; SizeX_mm: 1; SizeY_mm: 0.5; SizeZ_mm: 0.6; Value2: 0.063W; AEC Qualified: Y; VDC_V: 50V; AEC Category: Q200; AEC Grade: 0
R152 = CMP-0026992-3: as R146 on sheet PROC158A_FTDI
R154 = CMP-0026993-2: RES, 100, 5%, 0.1 W, AEC-Q200 Grade 0, 0402; Manufacturer: Panasonic; Power_W: 100mW; TempCo: 200 ppm/C; Value_Code: 100R; U/M: EA; Value: 100; EIA_Code: E24; SizeX_mm: 1; SizeY_mm: 0.5; SizeZ_mm: 0.6; Value2: 0.1W; AEC Qualified: Y; AEC Grade: 0; AEC Category: Q200
R155 = CMP-0025958-3: as R157 on sheet PROC158A_FTDI
R194 = CMP-0026413-2: RES, 4.87 k, 1%, 0.063 W, AEC-Q200 Grade 0, 0402; Manufacturer: Vishay-Dale; Power_W: 63mW; TempCo: 100 ppm/C; Value_Code: 4k87; Value: 4.87k; EIA_Code: E96; SizeX_mm: 1; SizeY_mm: 0.5; SizeZ_mm: 0.6; Value2: 0.063W; AEC Qualified: Y; VDC_V: 50V; AEC Category: Q200; AEC Grade: 0
R284 R285 = CMP-0078210-2: RES, 330 k, 1%, 0.063 W, AEC-Q200 Grade 0, 0402; Manufacturer: Vishay-Dale; SizeArea_mm2: 0.5; AEC Qualified: Y; AEC Category: Q200; Value: 330k; SizeZ_mm: 0.6; TempCo: 100 ppm/C; AEC Grade: 0; Power_W: 63mW; VDC_V: 50V; Value2: 0.063W; SizeX_mm: 1
R387-R389 = CMP-0026299-2: as R144 on sheet PROC158A_FTDI
U6 = CMP-0029856-2: Tiva C Series Microcontroller, 1024 KB Flash, 256 KB SRAM, 12 Bit, 20 Channels, -40 to 105 degC, 128-Pin TQFP (PDT), Green (RoHS & no Sb/Br), Tray; Manufacturer: Texas Instruments; ADC Channels: 20; CPU: ARM Cortex-M4; Flash: 1024 KB; ADC Resolution: 12 Bits; Max Speed: 120 MHz; SRAM: 256 KB; SizeAreaWB_mm2: 324.0; SizeArea_mm2: 256.0; SizeX_mm: 16.0; SizeZ_mm: 1.2; CompType: IC
U7 = CMP-0033001-1: Precision Micropower Shunt Voltage Reference, 0.5% accuracy, 2.5 V, 15 ppm / degC, 15 mA, -40 to 125 degC, 3-pin SOT-23 (DBZ), Green (RoHS & no Sb/Br); Manufacturer: Texas Instruments; Initial Accuracy @ 25/deg C(%): 0.5; Temp Coeff(Typ)(ppm/ degree C): 15; Temp Coeff(Max)(ppm/ degree C): 100; Rating: Catalog; Min Iz for Regulation(uA): 75; VO(V): 2.5
Y2 = CMP-0078214-2: Crystal, 16 MHz, 15 ppm, 8 pF, AEC-Q200 Grade 1, SMD; Manufacturer: NDK; TaMin_C: -40°C; Frequency Tolerance: 10 ppm; Frequency Stability: 150 ppm; Load Capacitance: 7.36 pF; Frequency_Fixed: 16MHz; TaMax_C: 125°C; AEC Qualified: N; AEC Grade: 1; AEC Category: Q200

## Sheet PROC158A_JTAG_EMU_Connector.SchDoc
size 431 x 279 mm; Date: Not shown in title block; ApprovedBy: Not shown in title block; CheckedBy: Not shown in title block; Author: Not shown in title block; CompanyName: Not shown in title block; Engineer: Not shown in title block; Organization: Not shown in title block; Address1: Not shown in title block; Address2: Not shown in title block; Address3: Not shown in title block; Address4: Not shown in title block; DocumentNumber: 20; Revision: Use project parameter SCH_Rev; SheetNumber: 20; SheetTotal: 24; PageSetup: Record=PageOptions¦CenterHorizontal=True¦CenterVertical=True¦PrintScale=1.00¦XCorrection=1.00¦YCorrection=1.00¦PrintKind=0¦BorderSize=5000000¦LeftOffset=0¦BottomOffset=0¦Orientation=2¦PaperLength=1000¦PaperWidth=1000¦Scale=100¦PaperSource=15¦PrintQuality=600¦MediaType=1¦DitherType=10¦PaperKind=Letter¦PrintScaleMode=1
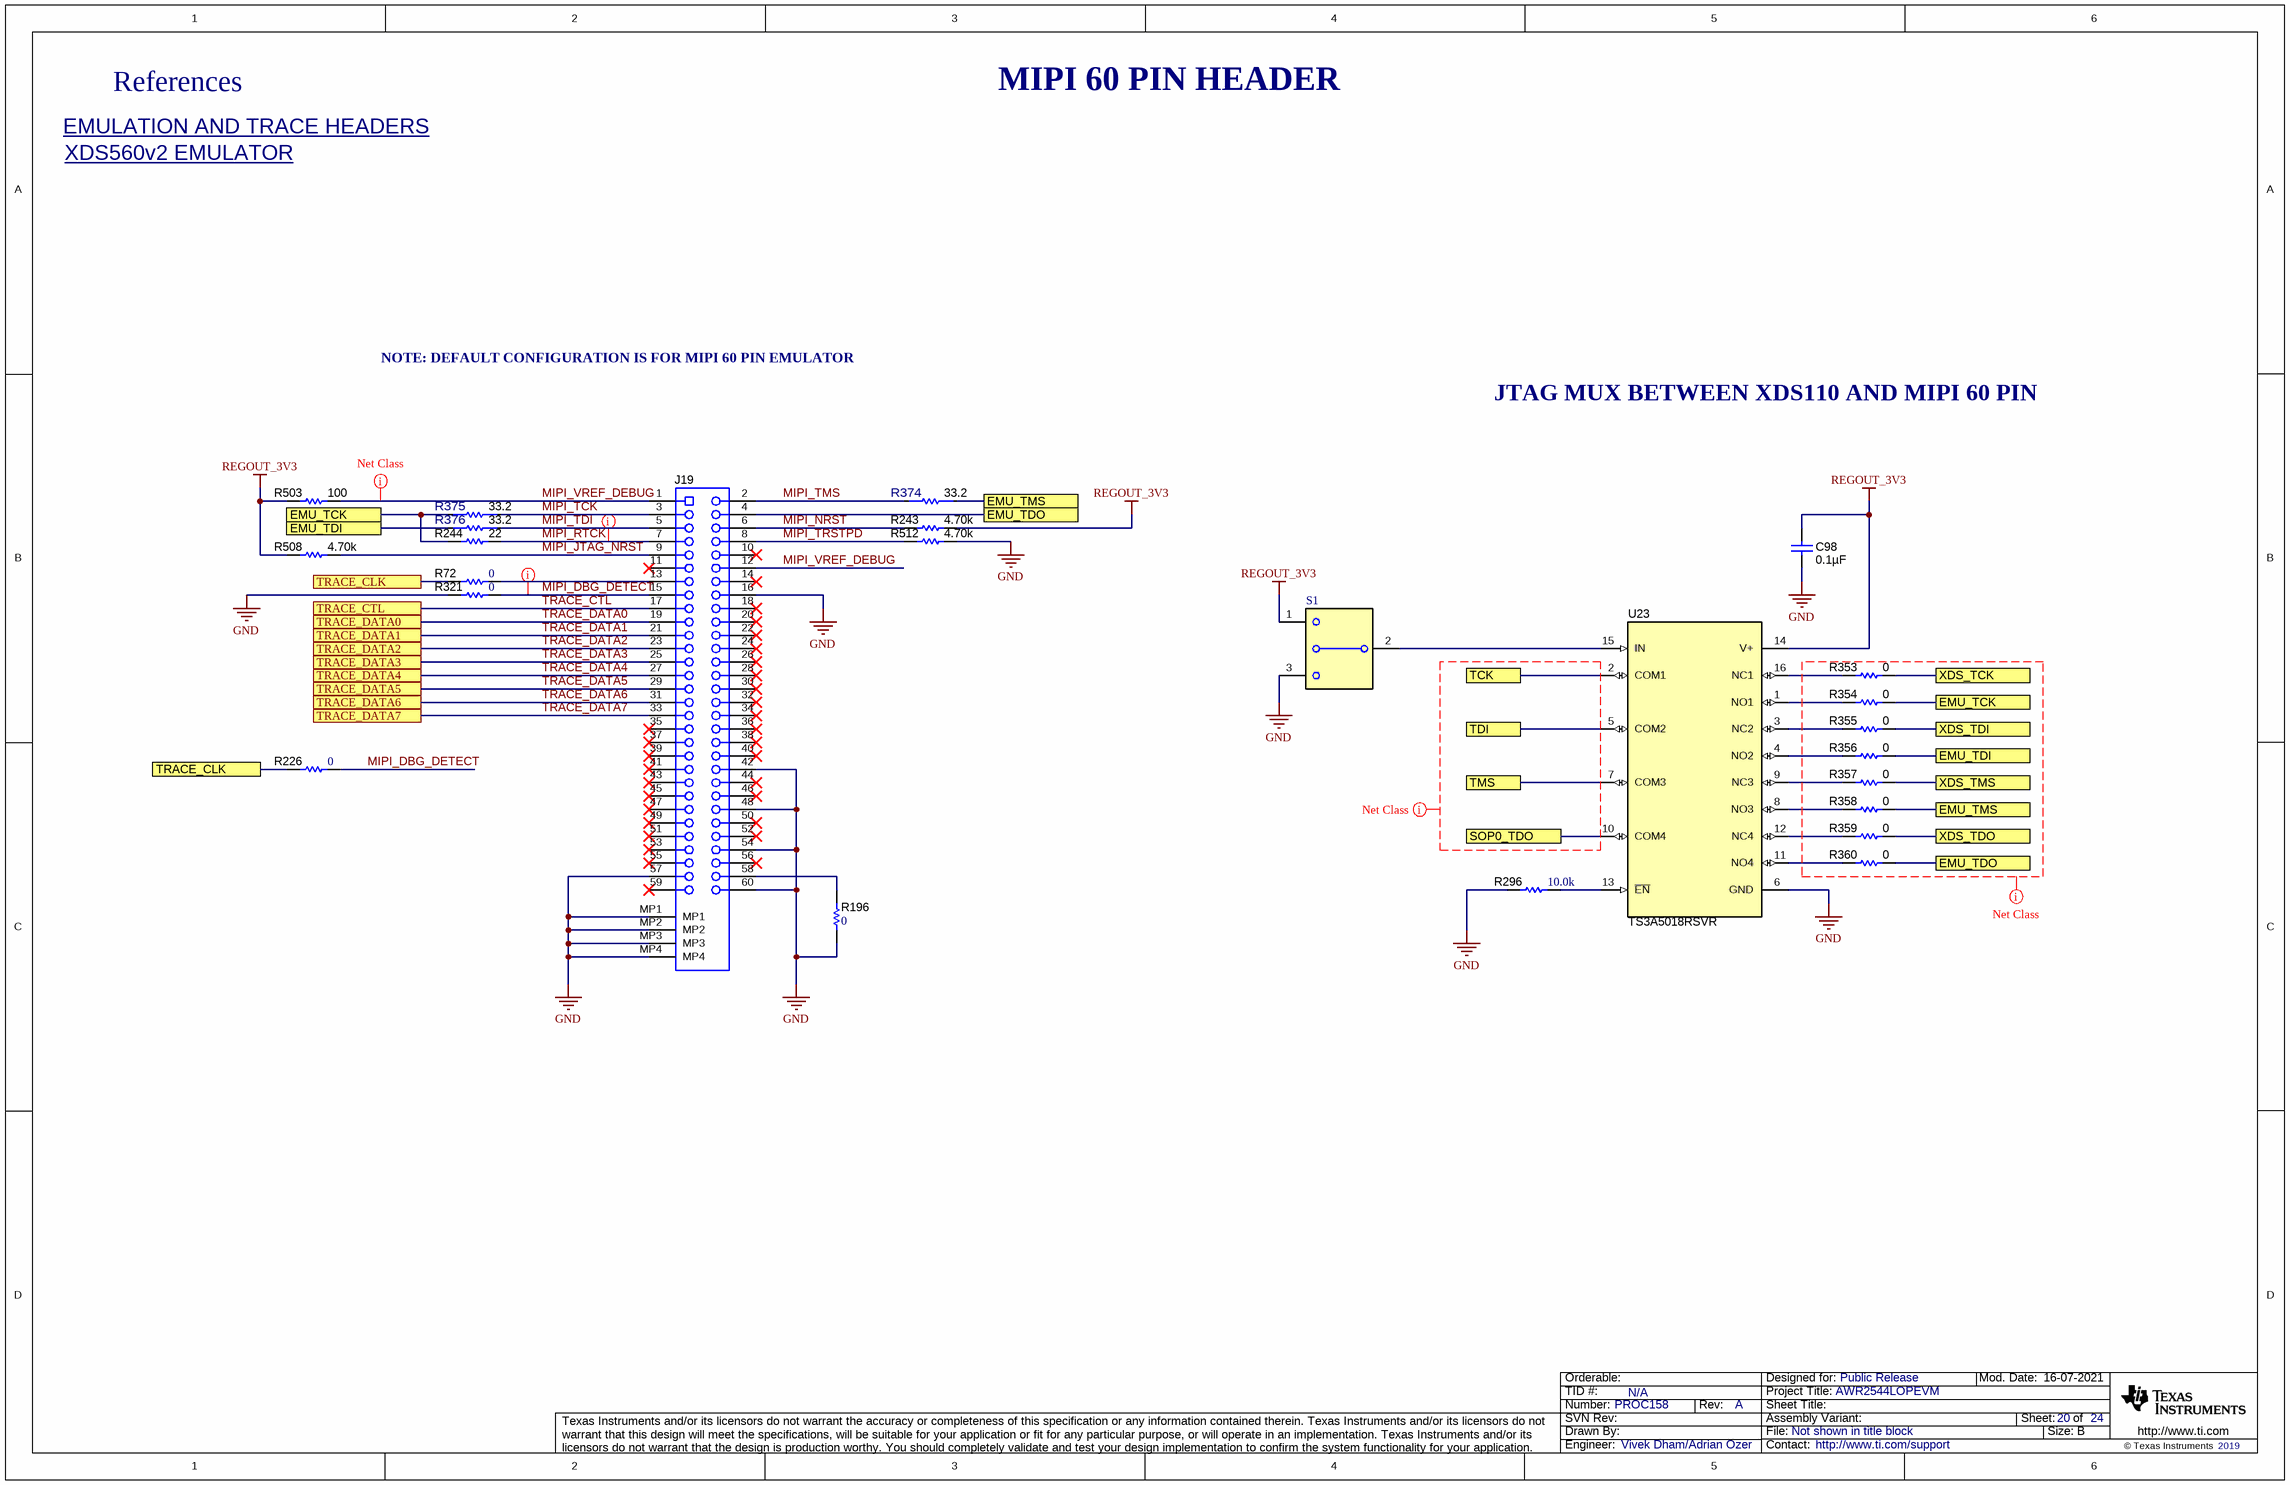
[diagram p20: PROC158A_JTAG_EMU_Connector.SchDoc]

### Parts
C98  ValueDisplayed: 0.1µF  [0402L]  (hidden comment: C0402C104K8RACTU)
J19  Receptacle_30x2_4MP_LeftRight  [Samtec_QSH-030-01-X-D-A]  (value not drawn)
R72  ValueDisplayed: 0  [0201L]  (hidden comment: CRCW02010000Z0ED)
R196  ValueDisplayed: 0  [0201L]  (hidden comment: CRCW02010000Z0ED)
R226  ValueDisplayed: 0  [0201L]  (hidden comment: CRCW02010000Z0ED)
R243  ValueDisplayed: 4.70k  [0201_033L]  (hidden comment: CRCW02014K70FKED)
R244  ValueDisplayed: 22  [0201L]  (hidden comment: ERJ-1GNJ220C)
R296  ValueDisplayed: 10.0k  [0402L]  (hidden comment: CRCW040210K0FKED)
R321  ValueDisplayed: 0  [0201L]  (hidden comment: CRCW02010000Z0ED)
R353  ValueDisplayed: 0  [0402L]  (hidden comment: ERJ-2GE0R00X)
R354  ValueDisplayed: 0  [0402L]  (hidden comment: ERJ-2GE0R00X)
R355  ValueDisplayed: 0  [0402L]  (hidden comment: ERJ-2GE0R00X)
R356  ValueDisplayed: 0  [0402L]  (hidden comment: ERJ-2GE0R00X)
R357  ValueDisplayed: 0  [0402L]  (hidden comment: ERJ-2GE0R00X)
R358  ValueDisplayed: 0  [0402L]  (hidden comment: ERJ-2GE0R00X)
R359  ValueDisplayed: 0  [0402L]  (hidden comment: ERJ-2GE0R00X)
R360  ValueDisplayed: 0  [0402L]  (hidden comment: ERJ-2GE0R00X)
R374  Res_ohm: 33.2  [FP-ERJ-1GNF33R2C_0201-MFG]  (hidden comment: ERJ-1GNF33R2C)
R375  Res_ohm: 33.2  [FP-ERJ-1GNF33R2C_0201-MFG]  (hidden comment: ERJ-1GNF33R2C)
R376  Res_ohm: 33.2  [FP-ERJ-1GNF33R2C_0201-MFG]  (hidden comment: ERJ-1GNF33R2C)
R503  ValueDisplayed: 100  [0201L]  (hidden comment: CRCW0201100RFKED)
R508  ValueDisplayed: 4.70k  [0201_033L]  (hidden comment: CRCW02014K70FKED)
R512  ValueDisplayed: 4.70k  [0201_033L]  (hidden comment: CRCW02014K70FKED)
S1  CJS-1201TA  [SW_CJS_1201A]  (value not drawn)
U23  TS3A5018RSVR  [RSV0016A]

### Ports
EMU_TCK, EMU_TDI, EMU_TDO, EMU_TMS, SOP0_TDO, TCK, TDI, TMS, TRACE_CLK, TRACE_CTL, TRACE_DATA0, TRACE_DATA1, TRACE_DATA2, TRACE_DATA3, TRACE_DATA4, TRACE_DATA5, TRACE_DATA6, TRACE_DATA7, XDS_TCK, XDS_TDI, XDS_TDO, XDS_TMS

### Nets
GND: C98.1 J19.16 J19.42 J19.48 J19.54 J19.57 J19.60 J19.MP1 J19.MP2 J19.MP3 J19.MP4 R196.2 R296.2 R321.1 R512.2 S1.3 U23.6(GND)
REGOUT_3V3: C98.2 R243.2 R503.1 R508.1 S1.1 U23.14(V+)
EMU_TCK: R244.1 R354.1 R375.2 ; port EMU_TCK
EMU_TDI: R356.1 R376.2 ; port EMU_TDI
EMU_TDO: J19.4 R360.1 ; port EMU_TDO
EMU_TMS: R358.1 R374.1 ; port EMU_TMS
MIPI_DBG_DETECT: J19.15 R226.2 R321.2
MIPI_JTAG_NRST: J19.9 R508.2
MIPI_NRST: J19.6 R243.1
MIPI_RTCK: J19.7 R244.2
MIPI_TCK: J19.3 R375.1
MIPI_TDI: J19.5 R376.1
MIPI_TMS: J19.2 R374.2
MIPI_TRSTPD: J19.8 R512.1
MIPI_VREF_DEBUG: J19.1 J19.12 R503.2
SOP0_TDO: U23.10(COM4) ; port SOP0_TDO
TCK: U23.2(COM1) ; port TCK
TDI: U23.5(COM2) ; port TDI
TMS: U23.7(COM3) ; port TMS
TRACE_CLK: R72.1 R226.1 ; port TRACE_CLK
TRACE_CTL: J19.17 ; port TRACE_CTL
TRACE_DATA0: J19.19 ; port TRACE_DATA0
TRACE_DATA1: J19.21 ; port TRACE_DATA1
TRACE_DATA2: J19.23 ; port TRACE_DATA2
TRACE_DATA3: J19.25 ; port TRACE_DATA3
TRACE_DATA4: J19.27 ; port TRACE_DATA4
TRACE_DATA5: J19.29 ; port TRACE_DATA5
TRACE_DATA6: J19.31 ; port TRACE_DATA6
TRACE_DATA7: J19.33 ; port TRACE_DATA7
XDS_TCK: R353.1 ; port XDS_TCK
XDS_TDI: R355.1 ; port XDS_TDI
XDS_TDO: R359.1 ; port XDS_TDO
XDS_TMS: R357.1 ; port XDS_TMS
NetJ19_13: J19.13 R72.2
NetJ19_58: J19.58 R196.1
NetR296_1: R296.1 U23.13(~{EN})
NetR353_2: R353.2 U23.16(NC1)
NetR354_2: R354.2 U23.1(NO1)
NetR355_2: R355.2 U23.3(NC2)
NetR356_2: R356.2 U23.4(NO2)
NetR357_2: R357.2 U23.9(NC3)
NetR358_2: R358.2 U23.8(NO3)
NetR359_2: R359.2 U23.12(NC4)
NetR360_2: R360.2 U23.11(NO4)
NetS1_2: S1.2(COM) U23.15(IN)

Not connected (* = marked no-connect by the designer): J19 10* 11* 14* 18* 20* 22* 24* 26* 28* 30* 32* 34* 35* 36* 37* 38* 39* 40* 41* 43* 44* 45* 46* 47* 49* 50* 51* 52* 53* 55* 56* 59*

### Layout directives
net class JTAG: (no net found under the mark), MIPI_RTCK
net class TRACE: MIPI_DBG_DETECT
net class PWR: MIPI_VREF_DEBUG

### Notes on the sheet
- References
- MIPI 60 PIN HEADER
- XDS560v2 EMULATOR <http://www.spectrumdigital.com/xds560v2-system-trace-jtag-emulator-with-target-adapters/>
- EMULATION AND TRACE HEADERS <http://www.ti.com/lit/ug/spru655i/spru655i.pdf>
- NOTE: DEFAULT CONFIGURATION IS FOR MIPI 60 PIN EMULATOR
- JTAG MUX BETWEEN XDS110 AND MIPI 60 PIN

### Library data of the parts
C98 = CMP-0078241-1: as C42 on sheet PROC158A_XDS110 Interface_1A
J19 = CMP-0075524-1: Receptacle, 0.5 mm, 30x2, Gold, TH; PartNumber: QSH-030-01-L-D-A; Manufacturer: Samtec; Pitch_mm: 0.5; Gender: Female; Shrouded: N; Row_Count: 2; RowSpacing_mm: 5.73; Green_Lifecycle: Active; Green_REACh: Passed; CNHeader: False
R72 R196 R226 R321 = CMP-0027008-4: RES, 0, 5%, 0.05 W, 0201; Manufacturer: Vishay-Dale; Power_W: 50mW; TempCo: ppm/C; Value_Code: 0000; Value: 0; EIA_Code: E24; SizeX_mm: 0.6; SizeY_mm: 0.3; SizeZ_mm: 0.26; Value2: 0.05W; SizeArea_mm2: 0.18; AEC Qualified: N; AEC Category: Q200
R243 R508 R512 = CMP-0027280-3: RES, 4.70 k, 1%, 0.05 W, 0201; Manufacturer: Vishay-Dale; Power_W: 50mW; TempCo: 100 ppm/C; Value_Code: 4k70; Value: 4.70k; Res_ohm: 4.7k; SizeX_mm: 0.6; SizeY_mm: 0.3; SizeZ_mm: 0.33; Value2: 0.05W; SizeArea_mm2: 0.18; AEC Qualified: N; VDC_V: 30V; AEC Category: Q200
R244 = CMP-0027015-3: RES, 22, 5%, 0.05 W, AEC-Q200 Grade 1, 0201; Manufacturer: Panasonic; Power_W: 50mW; TempCo: 200 ppm/C; Value_Code: 22R0; U/M: EA; Value: 22; EIA_Code: E24; SizeX_mm: 0.6; SizeY_mm: 0.3; SizeZ_mm: 0.26; Value2: 0.05W; SizeArea_mm2: 0.18; AEC Qualified: Y; AEC Grade: 1; AEC Category: Q200
R296 = CMP-0025958-3: as R157 on sheet PROC158A_FTDI
R353-R360 = CMP-0026992-3: as R146 on sheet PROC158A_FTDI
R374-R376 = CMP-0089575-2: Res Thick Film 0201 33.2 Ohm 1% 0.05W(1/20W) ±200ppm/C Pad SMD Automotive T/R; Manufacturer: Panasonic; TempCo: 200ppm/°C; VDC_V: 25V; AEC Qualified: Yes; SizeZ_mm: 0.26mm; Power_W: 50mW; AEC Grade: Grade 1; Value: 33.2
R503 = CMP-0083836-1: RES, 100, 1%, 0.05 W, 0201; Manufacturer: Vishay-Semiconductor; Value_Code: 100R; SizeAreaWB_mm2: 2.08; SizeArea_mm2: 0.18; AEC Qualified: N; AEC Category: Q200; Value: 100; SizeZ_mm: 0.26; EIA_Code: E96; TempCo: 100 ppm/C; Power_W: 50mW; SizeY_mm: 0.3; Value2: 0.05W; SizeX_mm: 0.6
S1 = CMP-0002159-2: Slide SW, SPDT 0.1A 50VDC; Manufacturer: Copal Electronics; CurrentRating_mA: 100A; SwitchFunction: On-Off-On; VDC_V: 50V; PositionCount: 1; CompType: Switch
U23 = CMP-0067415-1: 10-Ohm Quad SPDT Analog Switch, RSV0016A (UQFN-16); Alternate Manufacturer: Texas Instruments; SizeAreaWB_mm2: 10.08; U/M: EA; SizeZ_mm: 0.55; SizeX_mm: 1.8; SizeY_mm: 2.6; SizeArea_mm2: 4.68; CompType: IC

## Sheet PROC158A_Debug_Connector.SchDoc
size 431 x 279 mm; Date: Not shown in title block; ApprovedBy: Not shown in title block; CheckedBy: Not shown in title block; Author: Not shown in title block; CompanyName: Not shown in title block; Engineer: Not shown in title block; Organization: Not shown in title block; Address1: Not shown in title block; Address2: Not shown in title block; Address3: Not shown in title block; Address4: Not shown in title block; DocumentNumber: 21; Revision: Use project parameter SCH_Rev; SheetNumber: 21; SheetTotal: 24; PageSetup: Record=PageOptions¦CenterHorizontal=True¦CenterVertical=True¦PrintScale=1.00¦XCorrection=1.00¦YCorrection=1.00¦PrintKind=0¦BorderSize=5000000¦LeftOffset=0¦BottomOffset=0¦Orientation=2¦PaperLength=1000¦PaperWidth=1000¦Scale=100¦PaperSource=15¦PrintQuality=600¦MediaType=1¦DitherType=10¦PaperKind=Letter¦PrintScaleMode=1
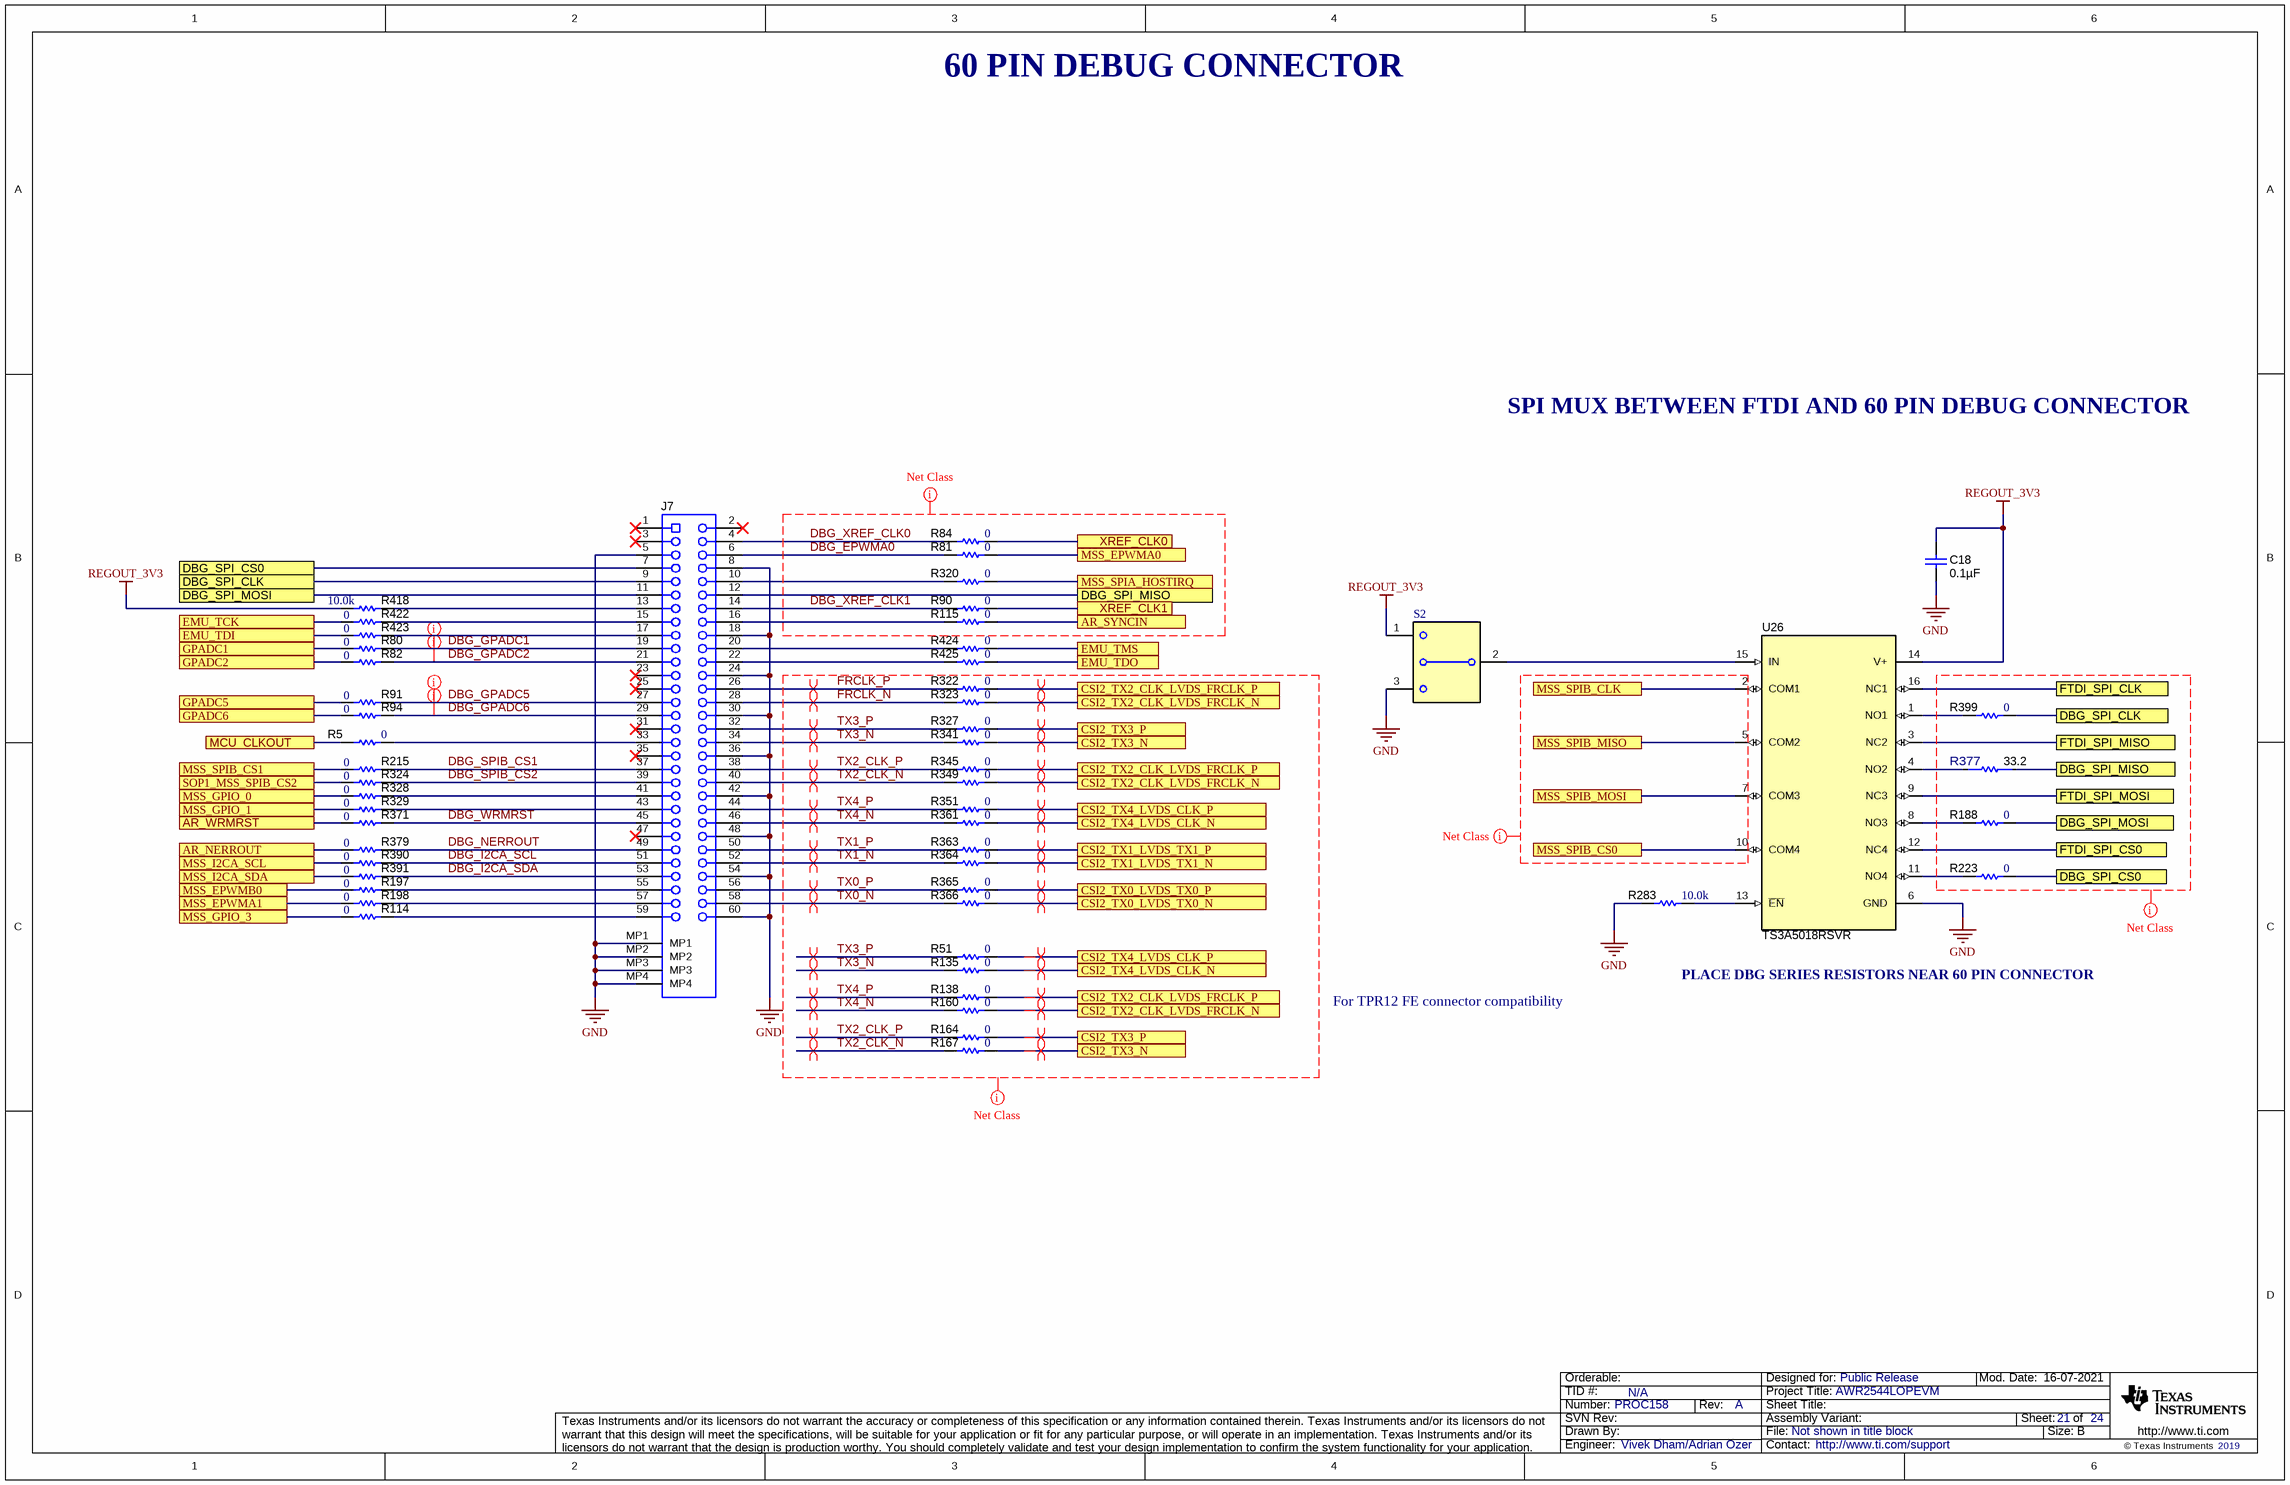
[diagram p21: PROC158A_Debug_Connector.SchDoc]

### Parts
C18  ValueDisplayed: 0.1µF  [0402L]  (hidden comment: C0402C104K8RACTU)
J7  QSH-030-01-L-D-A  [Samtec_QSH-030-01-X-D-A]  (value not drawn)
R5  ValueDisplayed: 0  [0201L]  (hidden comment: CRCW02010000Z0ED)
R51  ValueDisplayed: 0  [0201L]  (hidden comment: CRCW02010000Z0ED)
R80  ValueDisplayed: 0  [0201L]  (hidden comment: CRCW02010000Z0ED)
R81  ValueDisplayed: 0  [0201L]  (hidden comment: CRCW02010000Z0ED)
R82  ValueDisplayed: 0  [0201L]  (hidden comment: CRCW02010000Z0ED)
R84  ValueDisplayed: 0  [0201L]  (hidden comment: CRCW02010000Z0ED)
R90  ValueDisplayed: 0  [0201L]  (hidden comment: CRCW02010000Z0ED)
R91  ValueDisplayed: 0  [0201L]  (hidden comment: CRCW02010000Z0ED)
R94  ValueDisplayed: 0  [0201L]  (hidden comment: CRCW02010000Z0ED)
R114  ValueDisplayed: 0  [0201L]  (hidden comment: CRCW02010000Z0ED)
R115  ValueDisplayed: 0  [0201L]  (hidden comment: CRCW02010000Z0ED)
R135  ValueDisplayed: 0  [0201L]  (hidden comment: CRCW02010000Z0ED)
R138  ValueDisplayed: 0  [0201L]  (hidden comment: CRCW02010000Z0ED)
R160  ValueDisplayed: 0  [0201L]  (hidden comment: CRCW02010000Z0ED)
R164  ValueDisplayed: 0  [0201L]  (hidden comment: CRCW02010000Z0ED)
R167  ValueDisplayed: 0  [0201L]  (hidden comment: CRCW02010000Z0ED)
R188  ValueDisplayed: 0  [0201L]  (hidden comment: CRCW02010000Z0ED)
R197  ValueDisplayed: 0  [0201L]  (hidden comment: CRCW02010000Z0ED)
R198  ValueDisplayed: 0  [0201L]  (hidden comment: CRCW02010000Z0ED)
R215  ValueDisplayed: 0  [0201L]  (hidden comment: CRCW02010000Z0ED)
R223  ValueDisplayed: 0  [0201L]  (hidden comment: CRCW02010000Z0ED)
R283  ValueDisplayed: 10.0k  [0402L]  (hidden comment: CRCW040210K0FKED)
R320  ValueDisplayed: 0  [0201L]  (hidden comment: CRCW02010000Z0ED)
R322  ValueDisplayed: 0  [0201L]  (hidden comment: CRCW02010000Z0ED)
R323  ValueDisplayed: 0  [0201L]  (hidden comment: CRCW02010000Z0ED)
R324  ValueDisplayed: 0  [0201L]  (hidden comment: CRCW02010000Z0ED)
R327  ValueDisplayed: 0  [0201L]  (hidden comment: CRCW02010000Z0ED)
R328  ValueDisplayed: 0  [0201L]  (hidden comment: CRCW02010000Z0ED)
R329  ValueDisplayed: 0  [0201L]  (hidden comment: CRCW02010000Z0ED)
R341  ValueDisplayed: 0  [0201L]  (hidden comment: CRCW02010000Z0ED)
R345  ValueDisplayed: 0  [0201L]  (hidden comment: CRCW02010000Z0ED)
R349  ValueDisplayed: 0  [0201L]  (hidden comment: CRCW02010000Z0ED)
R351  ValueDisplayed: 0  [0201L]  (hidden comment: CRCW02010000Z0ED)
R361  ValueDisplayed: 0  [0201L]  (hidden comment: CRCW02010000Z0ED)
R363  ValueDisplayed: 0  [0201L]  (hidden comment: CRCW02010000Z0ED)
R364  ValueDisplayed: 0  [0201L]  (hidden comment: CRCW02010000Z0ED)
R365  ValueDisplayed: 0  [0201L]  (hidden comment: CRCW02010000Z0ED)
R366  ValueDisplayed: 0  [0201L]  (hidden comment: CRCW02010000Z0ED)
R371  ValueDisplayed: 0  [0201L]  (hidden comment: CRCW02010000Z0ED)
R377  Res_ohm: 33.2  [FP-ERJ-1GNF33R2C_0201-MFG]  (hidden comment: ERJ-1GNF33R2C)
R379  ValueDisplayed: 0  [0201L]  (hidden comment: CRCW02010000Z0ED)
R390  ValueDisplayed: 0  [0201L]  (hidden comment: CRCW02010000Z0ED)
R391  ValueDisplayed: 0  [0201L]  (hidden comment: CRCW02010000Z0ED)
R399  ValueDisplayed: 0  [0201L]  (hidden comment: CRCW02010000Z0ED)
R418  ValueDisplayed: 10.0k  [0402L]  (hidden comment: CRCW040210K0FKED)
R422  ValueDisplayed: 0  [0201L]  (hidden comment: CRCW02010000Z0ED)
R423  ValueDisplayed: 0  [0201L]  (hidden comment: CRCW02010000Z0ED)
R424  ValueDisplayed: 0  [0201L]  (hidden comment: CRCW02010000Z0ED)
R425  ValueDisplayed: 0  [0201L]  (hidden comment: CRCW02010000Z0ED)
S2  CJS-1201TA  [SW_CJS_1201A]  (value not drawn)
U26  TS3A5018RSVR  [RSV0016A]

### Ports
AR_NERROUT, AR_SYNCIN, AR_WRMRST, CSI2_TX0_LVDS_TX0_N, CSI2_TX0_LVDS_TX0_P, CSI2_TX1_LVDS_TX1_N, CSI2_TX1_LVDS_TX1_P, CSI2_TX2_CLK_LVDS_FRCLK_N, CSI2_TX2_CLK_LVDS_FRCLK_P, CSI2_TX3_N, CSI2_TX3_P, CSI2_TX4_LVDS_CLK_N, CSI2_TX4_LVDS_CLK_P, DBG_SPI_CLK, DBG_SPI_CS0, DBG_SPI_MISO, DBG_SPI_MOSI, EMU_TCK, EMU_TDI, EMU_TDO, EMU_TMS, FTDI_SPI_CLK, FTDI_SPI_CS0, FTDI_SPI_MISO, FTDI_SPI_MOSI, GPADC1, GPADC2, GPADC5, GPADC6, MCU_CLKOUT, MSS_EPWMA0, MSS_EPWMA1, MSS_EPWMB0, MSS_GPIO_0, MSS_GPIO_1, MSS_GPIO_3, MSS_I2CA_SCL, MSS_I2CA_SDA, MSS_SPIA_HOSTIRQ, MSS_SPIB_CLK, MSS_SPIB_CS0, MSS_SPIB_CS1, MSS_SPIB_MISO, MSS_SPIB_MOSI, SOP1_MSS_SPIB_CS2, XREF_CLK0, XREF_CLK1

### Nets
GND: C18.1 J7.5 J7.8 J7.18 J7.24 J7.30 J7.36 J7.42 J7.48 J7.54 J7.60 J7.MP1 J7.MP2 J7.MP3 J7.MP4 R283.2 S2.3 U26.6(GND)
REGOUT_3V3: C18.2 R418.2 S2.1 U26.14(V+)
AR_NERROUT: R379.1 ; port AR_NERROUT
AR_SYNCIN: R115.1 ; port AR_SYNCIN
AR_WRMRST: R371.1 ; port AR_WRMRST
CSI2_TX0_LVDS_TX0_N: R366.2 ; port CSI2_TX0_LVDS_TX0_N
CSI2_TX0_LVDS_TX0_P: R365.2 ; port CSI2_TX0_LVDS_TX0_P
CSI2_TX1_LVDS_TX1_N: R364.2 ; port CSI2_TX1_LVDS_TX1_N
CSI2_TX1_LVDS_TX1_P: R363.2 ; port CSI2_TX1_LVDS_TX1_P
CSI2_TX2_CLK_LVDS_FRCLK_N: R160.2 R323.2 R349.2 ; port CSI2_TX2_CLK_LVDS_FRCLK_N
CSI2_TX2_CLK_LVDS_FRCLK_P: R138.2 R322.2 R345.2 ; port CSI2_TX2_CLK_LVDS_FRCLK_P
CSI2_TX3_N: R167.2 R341.2 ; port CSI2_TX3_N
CSI2_TX3_P: R164.2 R327.2 ; port CSI2_TX3_P
CSI2_TX4_LVDS_CLK_N: R135.2 R361.2 ; port CSI2_TX4_LVDS_CLK_N
CSI2_TX4_LVDS_CLK_P: R51.2 R351.2 ; port CSI2_TX4_LVDS_CLK_P
DBG_EPWMA0: J7.6 R81.2
DBG_GPADC1: J7.19 R80.2
DBG_GPADC2: J7.21 R82.2
DBG_GPADC5: J7.27 R91.2
DBG_GPADC6: J7.29 R94.2
DBG_I2CA_SCL: J7.51 R390.2
DBG_I2CA_SDA: J7.53 R391.2
DBG_NERROUT: J7.49 R379.2
DBG_SPI_CLK: J7.9 R399.2 ; port DBG_SPI_CLK
DBG_SPI_CS0: J7.7 R223.2 ; port DBG_SPI_CS0
DBG_SPI_MISO: J7.12 R377.1 ; port DBG_SPI_MISO
DBG_SPI_MOSI: J7.11 R188.2 ; port DBG_SPI_MOSI
DBG_SPIB_CS1: J7.37 R215.2
DBG_SPIB_CS2: J7.39 R324.2
DBG_WRMRST: J7.45 R371.2
DBG_XREF_CLK0: J7.4 R84.2
DBG_XREF_CLK1: J7.14 R90.2
EMU_TCK: R422.1 ; port EMU_TCK
EMU_TDI: R423.1 ; port EMU_TDI
EMU_TDO: R425.2 ; port EMU_TDO
EMU_TMS: R424.2 ; port EMU_TMS
FRCLK_N: J7.28 R323.1
FRCLK_P: J7.26 R322.1
FTDI_SPI_CLK: U26.16(NC1) ; port FTDI_SPI_CLK
FTDI_SPI_CS0: U26.12(NC4) ; port FTDI_SPI_CS0
FTDI_SPI_MISO: U26.3(NC2) ; port FTDI_SPI_MISO
FTDI_SPI_MOSI: U26.9(NC3) ; port FTDI_SPI_MOSI
GPADC1: R80.1 ; port GPADC1
GPADC2: R82.1 ; port GPADC2
GPADC5: R91.1 ; port GPADC5
GPADC6: R94.1 ; port GPADC6
MCU_CLKOUT: R5.2 ; port MCU_CLKOUT
MSS_EPWMA0: R81.1 ; port MSS_EPWMA0
MSS_EPWMA1: R198.1 ; port MSS_EPWMA1
MSS_EPWMB0: R197.1 ; port MSS_EPWMB0
MSS_GPIO_0: R328.1 ; port MSS_GPIO_0
MSS_GPIO_1: R329.1 ; port MSS_GPIO_1
MSS_GPIO_3: R114.1 ; port MSS_GPIO_3
MSS_I2CA_SCL: R390.1 ; port MSS_I2CA_SCL
MSS_I2CA_SDA: R391.1 ; port MSS_I2CA_SDA
MSS_SPIA_HOSTIRQ: R320.1 ; port MSS_SPIA_HOSTIRQ
MSS_SPIB_CLK: U26.2(COM1) ; port MSS_SPIB_CLK
MSS_SPIB_CS0: U26.10(COM4) ; port MSS_SPIB_CS0
MSS_SPIB_CS1: R215.1 ; port MSS_SPIB_CS1
MSS_SPIB_MISO: U26.5(COM2) ; port MSS_SPIB_MISO
MSS_SPIB_MOSI: U26.7(COM3) ; port MSS_SPIB_MOSI
SOP1_MSS_SPIB_CS2: R324.1 ; port SOP1_MSS_SPIB_CS2
TX0_N: J7.58 R366.1
TX0_P: J7.56 R365.1
TX1_N: J7.52 R364.1
TX1_P: J7.50 R363.1
TX2_CLK_N: J7.40 R167.1 R349.1
TX2_CLK_P: J7.38 R164.1 R345.1
TX3_N: J7.34 R135.1 R341.1
TX3_P: J7.32 R51.1 R327.1
TX4_N: J7.46 R160.1 R361.1
TX4_P: J7.44 R138.1 R351.1
XREF_CLK0: R84.1 ; port XREF_CLK0
XREF_CLK1: R90.1 ; port XREF_CLK1
NetJ7_10: J7.10 R320.2
NetJ7_13: J7.13 R418.1
NetJ7_15: J7.15 R422.2
NetJ7_16: J7.16 R115.2
NetJ7_17: J7.17 R423.2
NetJ7_20: J7.20 R424.1
NetJ7_22: J7.22 R425.1
NetJ7_33: J7.33 R5.1
NetJ7_41: J7.41 R328.2
NetJ7_43: J7.43 R329.2
NetJ7_55: J7.55 R197.2
NetJ7_57: J7.57 R198.2
NetJ7_59: J7.59 R114.2
NetR188_1: R188.1 U26.8(NO3)
NetR223_1: R223.1 U26.11(NO4)
NetR283_1: R283.1 U26.13(~{EN})
NetR377_2: R377.2 U26.4(NO2)
NetR399_1: R399.1 U26.1(NO1)
NetS2_2: S2.2(COM) U26.15(IN)

Not connected (* = marked no-connect by the designer): J7 1* 2* 3* 23* 25* 31* 35* 47*

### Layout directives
net class CSI: FRCLK_N, FRCLK_P, TX0_N, TX0_P, TX1_N, TX1_P, TX2_CLK_N, TX2_CLK_P, TX3_N, TX3_P, TX4_N, TX4_P
net class CLKOUT: DBG_EPWMA0, DBG_XREF_CLK0, DBG_XREF_CLK1
net class JTAG: (no net found under the mark)
net class GPADC: DBG_GPADC1, DBG_GPADC2, DBG_GPADC5, DBG_GPADC6
differential pair: CSI2_TX0_LVDS_TX0_N, CSI2_TX0_LVDS_TX0_P, CSI2_TX1_LVDS_TX1_N, CSI2_TX1_LVDS_TX1_P, CSI2_TX2_CLK_LVDS_FRCLK_N, CSI2_TX2_CLK_LVDS_FRCLK_P, CSI2_TX3_N, CSI2_TX3_P, CSI2_TX4_LVDS_CLK_N, CSI2_TX4_LVDS_CLK_P, FRCLK_N, FRCLK_P, TX0_N, TX0_P, TX1_N, TX1_P, TX2_CLK_N, TX2_CLK_P, TX3_N, TX3_P, TX4_N, TX4_P

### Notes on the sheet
- 60 PIN DEBUG CONNECTOR
- SPI MUX BETWEEN FTDI AND 60 PIN DEBUG CONNECTOR
- For TPR12 FE connector compatibility
- PLACE DBG SERIES RESISTORS NEAR 60 PIN CONNECTOR

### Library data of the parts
C18 = CMP-0078241-1: as C42 on sheet PROC158A_XDS110 Interface_1A
J7 = CMP-0075524-1: Receptacle, 0.5 mm, 30x2, Gold, TH; Manufacturer: Samtec; Pitch_mm: 0.5; Gender: Female; Green_REACh: Passed; CT: False; Shrouded: N; RowSpacing_mm: 5.73; Green_Lifecycle: Active; Row_Count: 2
R5 R51 R80-R82 R84 R90 R91 R94 R114 R115 R135 R138 R160 R164 R167 R188 R197 R198 R215 R223 R320 R322-R324 R327-R329 R341 R345 R349 R351 R361 R363-R366 R371 R379 R390 R391 R399 R422-R425 = CMP-0027008-4: as R72 on sheet PROC158A_JTAG_EMU_Connector
R283 R418 = CMP-0025958-3: as R157 on sheet PROC158A_FTDI
R377 = CMP-0089575-2: as R374-R376 on sheet PROC158A_JTAG_EMU_Connector
S2 = CMP-0002159-2: as S1 on sheet PROC158A_JTAG_EMU_Connector
U26 = CMP-0067415-1: as U23 on sheet PROC158A_JTAG_EMU_Connector

## Sheet PROC158A_Current_Sensors.SchDoc
size 431 x 279 mm; Date: Not shown in title block; ApprovedBy: Not shown in title block; CheckedBy: Not shown in title block; Author: Not shown in title block; CompanyName: Not shown in title block; Engineer: Not shown in title block; Organization: Not shown in title block; Address1: Not shown in title block; Address2: Not shown in title block; Address3: Not shown in title block; Address4: Not shown in title block; DocumentNumber: 23; Revision: Use project parameter SCH_Rev; SheetNumber: 22; SheetTotal: 24; PageSetup: Record=PageOptions¦CenterHorizontal=True¦CenterVertical=True¦PrintScale=1.00¦XCorrection=1.00¦YCorrection=1.00¦PrintKind=0¦BorderSize=5000000¦LeftOffset=0¦BottomOffset=0¦Orientation=2¦PaperLength=1000¦PaperWidth=1000¦Scale=100¦PaperSource=15¦PrintQuality=600¦MediaType=1¦DitherType=10¦PaperKind=Letter¦PrintScaleMode=1
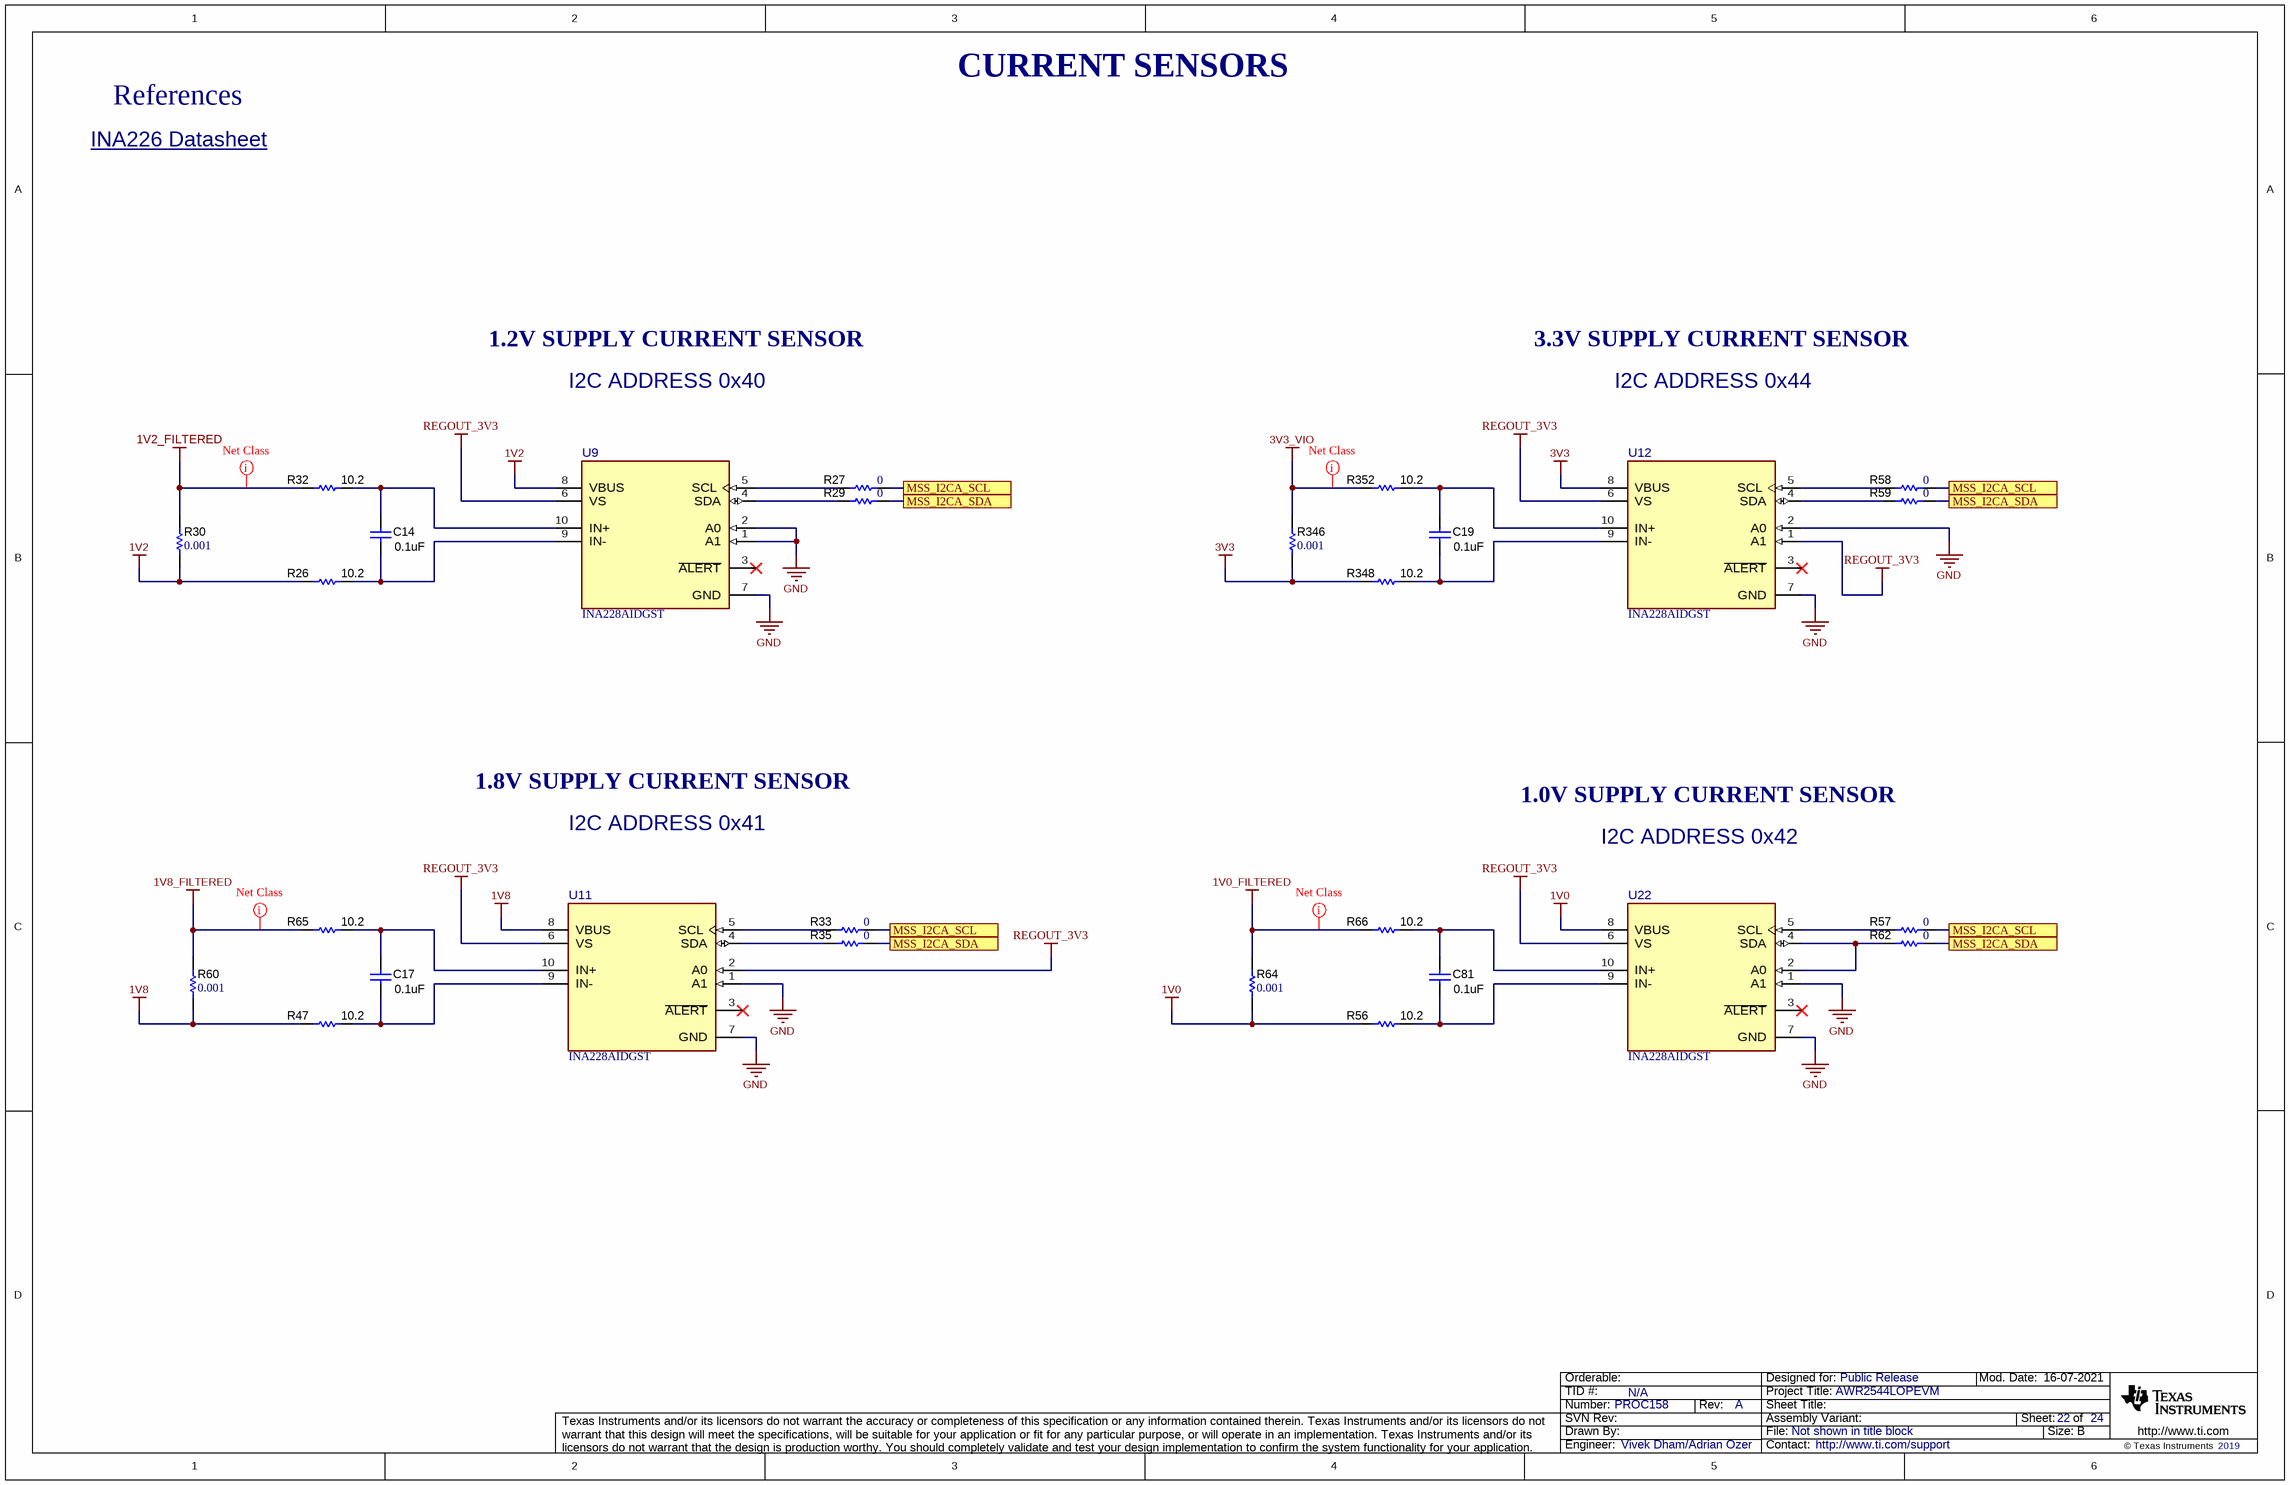
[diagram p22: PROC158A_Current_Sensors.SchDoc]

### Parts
C14  ValueDisplayed: 0.1uF  [0402L]  (hidden comment: GCM155R71A104KA55D)
C17  ValueDisplayed: 0.1uF  [0402L]  (hidden comment: GCM155R71A104KA55D)
C19  ValueDisplayed: 0.1uF  [0402L]  (hidden comment: GCM155R71A104KA55D)
C81  ValueDisplayed: 0.1uF  [0402L]  (hidden comment: GCM155R71A104KA55D)
R26  ValueDisplayed: 10.2  [0402L]  (hidden comment: CRCW040210R2FKED)
R27  ValueDisplayed: 0  [0402L]  (hidden comment: ERJ-2GE0R00X)
R29  ValueDisplayed: 0  [0402L]  (hidden comment: ERJ-2GE0R00X)
R30  ValueDisplayed: 0.001  [1206L]  (hidden comment: CSNL1206FT1L00)
R32  ValueDisplayed: 10.2  [0402L]  (hidden comment: CRCW040210R2FKED)
R33  ValueDisplayed: 0  [0402L]  (hidden comment: ERJ-2GE0R00X)
R35  ValueDisplayed: 0  [0402L]  (hidden comment: ERJ-2GE0R00X)
R47  ValueDisplayed: 10.2  [0402L]  (hidden comment: CRCW040210R2FKED)
R56  ValueDisplayed: 10.2  [0402L]  (hidden comment: CRCW040210R2FKED)
R57  ValueDisplayed: 0  [0402L]  (hidden comment: ERJ-2GE0R00X)
R58  ValueDisplayed: 0  [0402L]  (hidden comment: ERJ-2GE0R00X)
R59  ValueDisplayed: 0  [0402L]  (hidden comment: ERJ-2GE0R00X)
R60  ValueDisplayed: 0.001  [1206L]  (hidden comment: CSNL1206FT1L00)
R62  ValueDisplayed: 0  [0402L]  (hidden comment: ERJ-2GE0R00X)
R64  ValueDisplayed: 0.001  [1206L]  (hidden comment: CSNL1206FT1L00)
R65  ValueDisplayed: 10.2  [0402L]  (hidden comment: CRCW040210R2FKED)
R66  ValueDisplayed: 10.2  [0402L]  (hidden comment: CRCW040210R2FKED)
R346  ValueDisplayed: 0.001  [1206L]  (hidden comment: CSNL1206FT1L00)
R348  ValueDisplayed: 10.2  [0402L]  (hidden comment: CRCW040210R2FKED)
R352  ValueDisplayed: 10.2  [0402L]  (hidden comment: CRCW040210R2FKED)
U9  INA228AIDGST  [DGS0010A-MFG]
U11  INA228AIDGST  [DGS0010A-MFG]
U12  INA228AIDGST  [DGS0010A-MFG]
U22  INA228AIDGST  [DGS0010A-MFG]

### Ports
MSS_I2CA_SCL, MSS_I2CA_SDA

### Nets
1V0: R56.1 R64.1 U22.8(VBUS)
1V0_FILTERED: R64.2 R66.1
1V2: R26.1 R30.1 U9.8(VBUS)
1V2_FILTERED: R30.2 R32.1
1V8: R47.1 R60.1 U11.8(VBUS)
1V8_FILTERED: R60.2 R65.1
3V3: R346.1 R348.1 U12.8(VBUS)
3V3_VIO: R346.2 R352.1
GND: U9.1(A1) U9.2(A0) U9.7(GND) U11.1(A1) U11.7(GND) U12.2(A0) U12.7(GND) U22.1(A1) U22.7(GND)
REGOUT_3V3: U9.6(VS) U11.2(A0) U11.6(VS) U12.1(A1) U12.6(VS) U22.6(VS)
MSS_I2CA_SCL: R27.2 R33.2 R57.2 R58.2 ; port MSS_I2CA_SCL
MSS_I2CA_SDA: R29.2 R35.2 R59.2 R62.2 ; port MSS_I2CA_SDA
NetC14_1: C14.1 R32.2 U9.10(IN+)
NetC14_2: C14.2 R26.2 U9.9(IN-)
NetC17_1: C17.1 R65.2 U11.10(IN+)
NetC17_2: C17.2 R47.2 U11.9(IN-)
NetC19_1: C19.1 R352.2 U12.10(IN+)
NetC19_2: C19.2 R348.2 U12.9(IN-)
NetC81_1: C81.1 R66.2 U22.10(IN+)
NetC81_2: C81.2 R56.2 U22.9(IN-)
NetR27_1: R27.1 U9.5(SCL)
NetR29_1: R29.1 U9.4(SDA)
NetR33_1: R33.1 U11.5(SCL)
NetR35_1: R35.1 U11.4(SDA)
NetR57_1: R57.1 U22.5(SCL)
NetR58_1: R58.1 U12.5(SCL)
NetR59_1: R59.1 U12.4(SDA)
NetR62_1: R62.1 U22.2(A0) U22.4(SDA)

Not connected (* = marked no-connect by the designer): U9 3(~{ALERT})*; U11 3(~{ALERT})*; U12 3(~{ALERT})*; U22 3(~{ALERT})*

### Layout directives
net class PWR: 1V0_FILTERED, 1V2_FILTERED, 1V8_FILTERED, 3V3_VIO

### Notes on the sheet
- CURRENT SENSORS
- References
- INA226 Datasheet <http://www.ti.com/lit/ds/symlink/ina226.pdf>
- 1.2V SUPPLY CURRENT SENSOR
- 3.3V SUPPLY CURRENT SENSOR
- I2C ADDRESS 0x40
- I2C ADDRESS 0x44
- 1.8V SUPPLY CURRENT SENSOR
- I2C ADDRESS 0x41
- 1.0V SUPPLY CURRENT SENSOR
- I2C ADDRESS 0x42

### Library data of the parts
C14 C17 C19 C81 = CMP-0006350-2: CAP, CERM, 0.1 uF, 10 V, +/- 10%, X7R, AEC-Q200 Grade 1, 0402; Manufacturer: MuRata; TaMin_C: -55°C; Polarized: N; SizeAreaWB_mm2: 3; Value1: Unknown; U/M: EA; Value: 0.1uF; TaMax_C: 125°C; SizeZ_mm: 0.6; SizeX_mm: 1; SizeY_mm: 0.5; Cap_Case: 0402; Value2: 10V; AEC Qualified: Y; Cap_F: 100nF; AEC Category: Q200
R26 R32 R47 R56 R65 R66 R348 R352 = CMP-0025964-3: RES, 10.2, 1%, 0.063 W, AEC-Q200 Grade 0, 0402; Manufacturer: Vishay-Dale; Power_W: 63mW; TempCo: 100 ppm/C; Value_Code: 10R2; Value: 10.2; EIA_Code: E96; SizeX_mm: 1; SizeY_mm: 0.5; SizeZ_mm: 0.6; Value2: 0.063W; AEC Qualified: Y; VDC_V: 50V; AEC Category: Q200; AEC Grade: 0
R27 R29 R33 R35 R57-R59 R62 = CMP-0026992-3: as R146 on sheet PROC158A_FTDI
R30 R60 R64 R346 = CMP-0017253-2: RES, 0.001, 1%, 1 W, AEC-Q200 Grade 0, 1206; Manufacturer: Stackpole Electronics Inc; Power_W: 1W; TempCo: 50 ppm/C; Value_Code: 1L000; U/M: EA; Value: 0.001; EIA_Code: E96; Res_ohm: 1m; SizeX_mm: 3.2; SizeY_mm: 1.6; SizeZ_mm: 1.35; SizeArea_mm2: 5.12; AEC Qualified: Y; AEC Grade: 0; AEC Category: Q200
U9 U11 U12 U22 = CMP-0098432-1: Current Sense Amplifier 1 Circuit 10-VSSOP; Manufacturer: Texas Instruments; SizeZ_mm: 1.1mm; AEC Qualified: No; Input Bias Current: 0.01uA; Input Offset Voltage: 1mV; Max Supply Voltage: 5.5V; Min Supply Voltage: 2.7V; Nominal Supply Current: 640uA; Number Of Channels: 1; Standoff Height: 0.05mm; TaMax_C: +125°C; TaMin_C: -40°C; TJmax_C: +150°C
